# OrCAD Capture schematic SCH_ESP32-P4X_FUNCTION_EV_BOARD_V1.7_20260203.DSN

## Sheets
1 01_DESIGNBLOCK: title: ESP32-P4X_FUNCTION_EV_BOARD; rev: 1.7; note: 01_DESIGNBLOCK
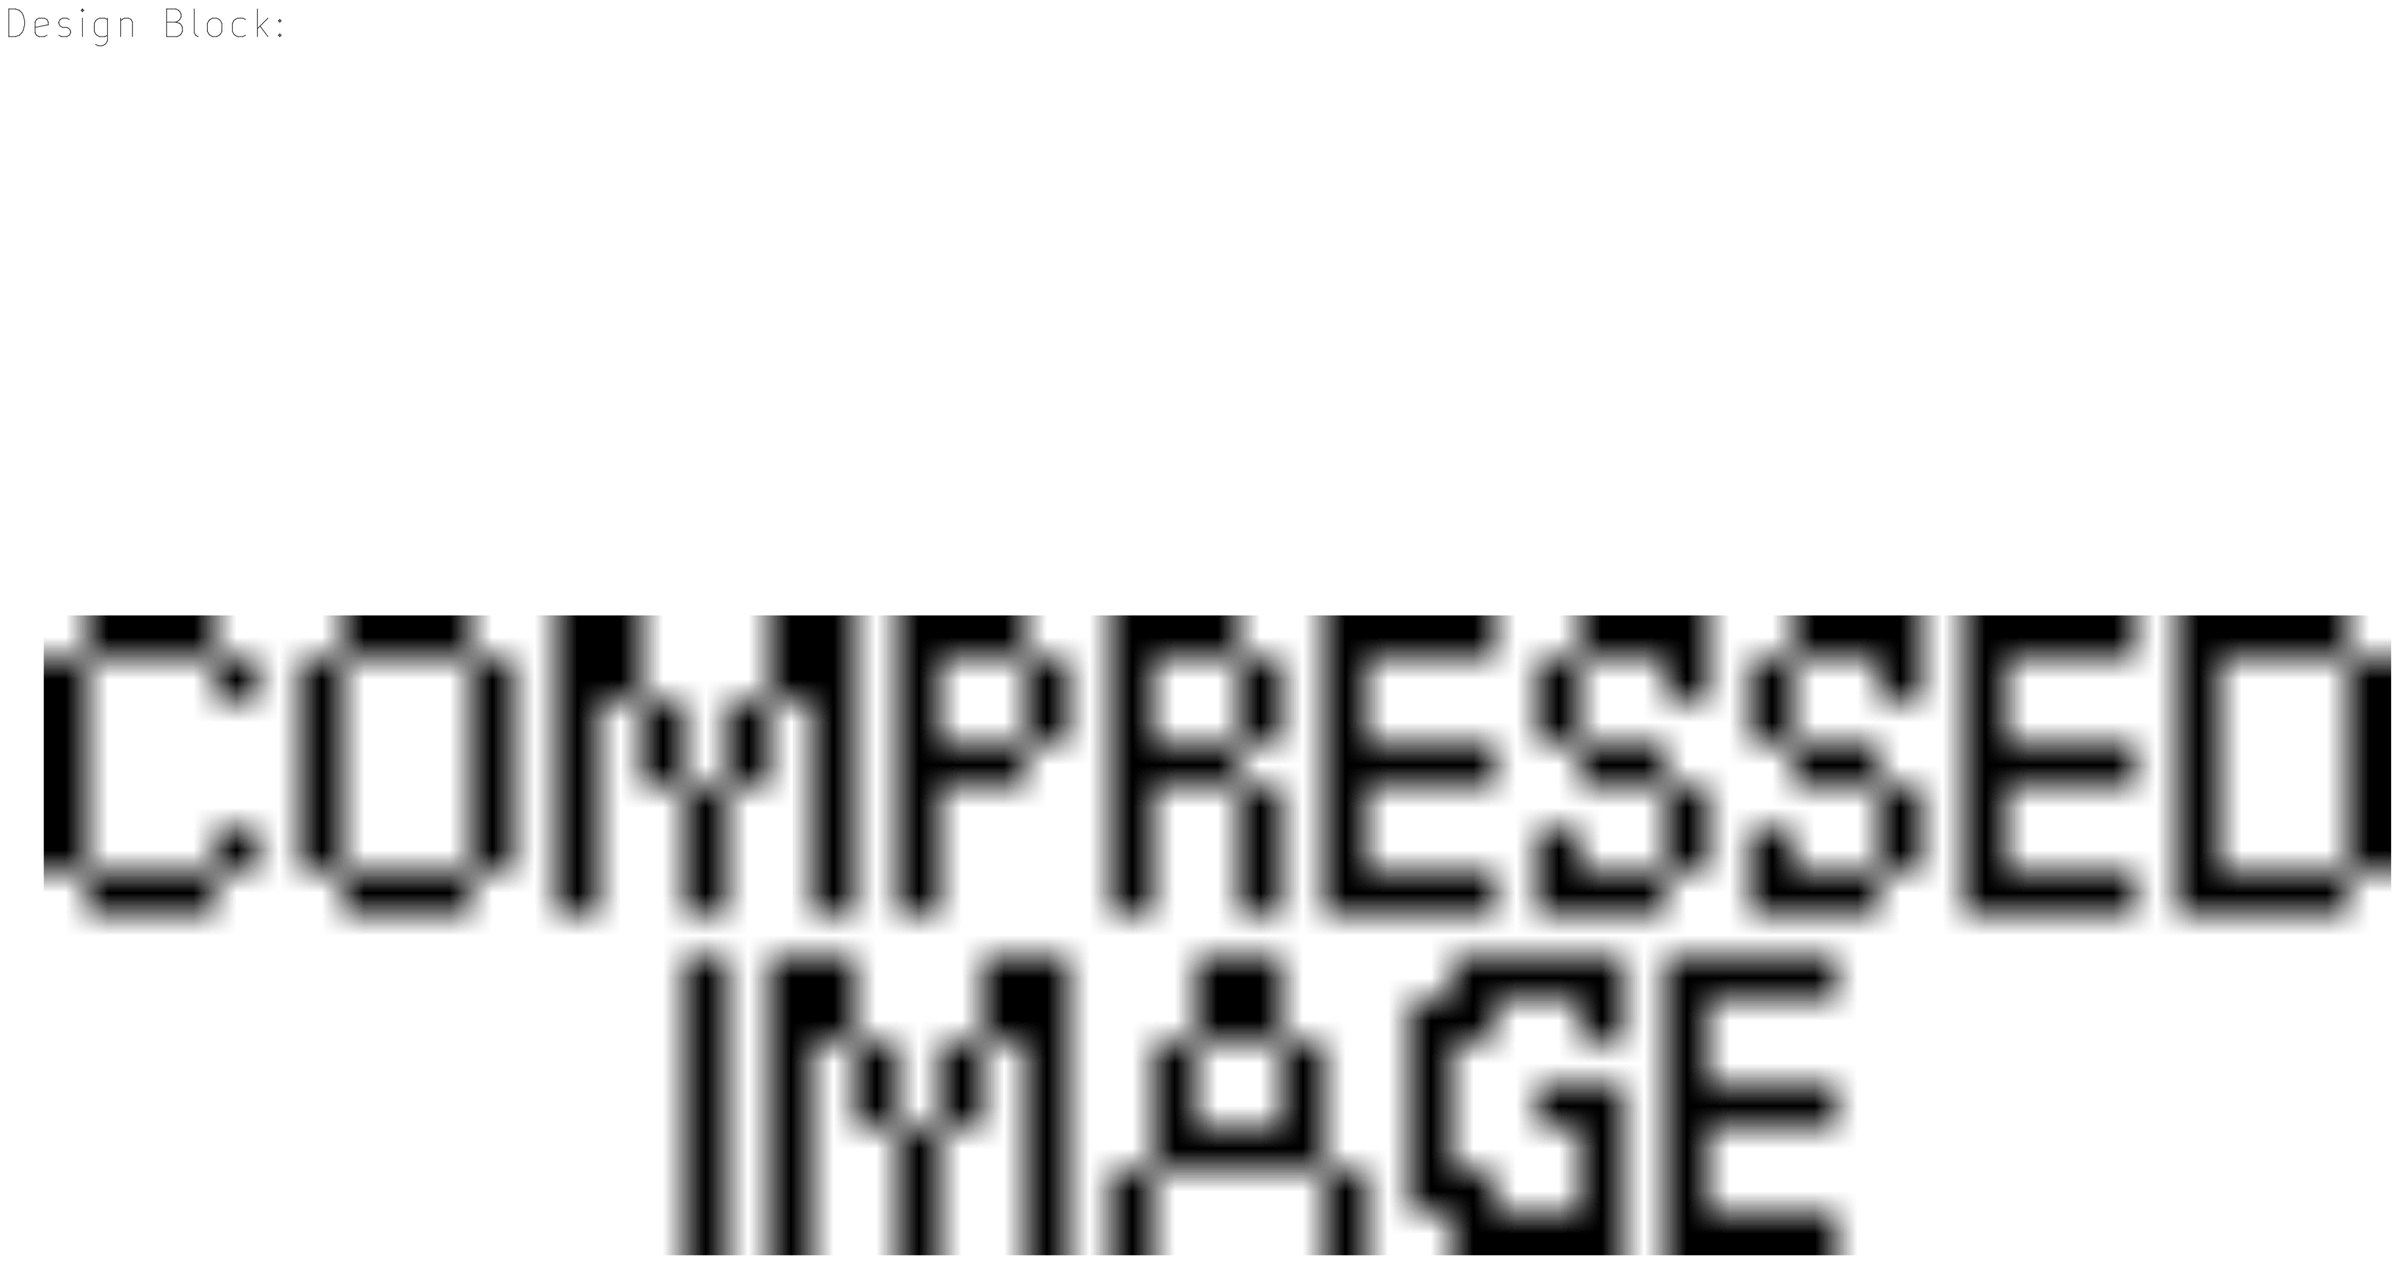
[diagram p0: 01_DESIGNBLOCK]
2 02_ESP32-P4: size C; note: 02_ESP32-P4
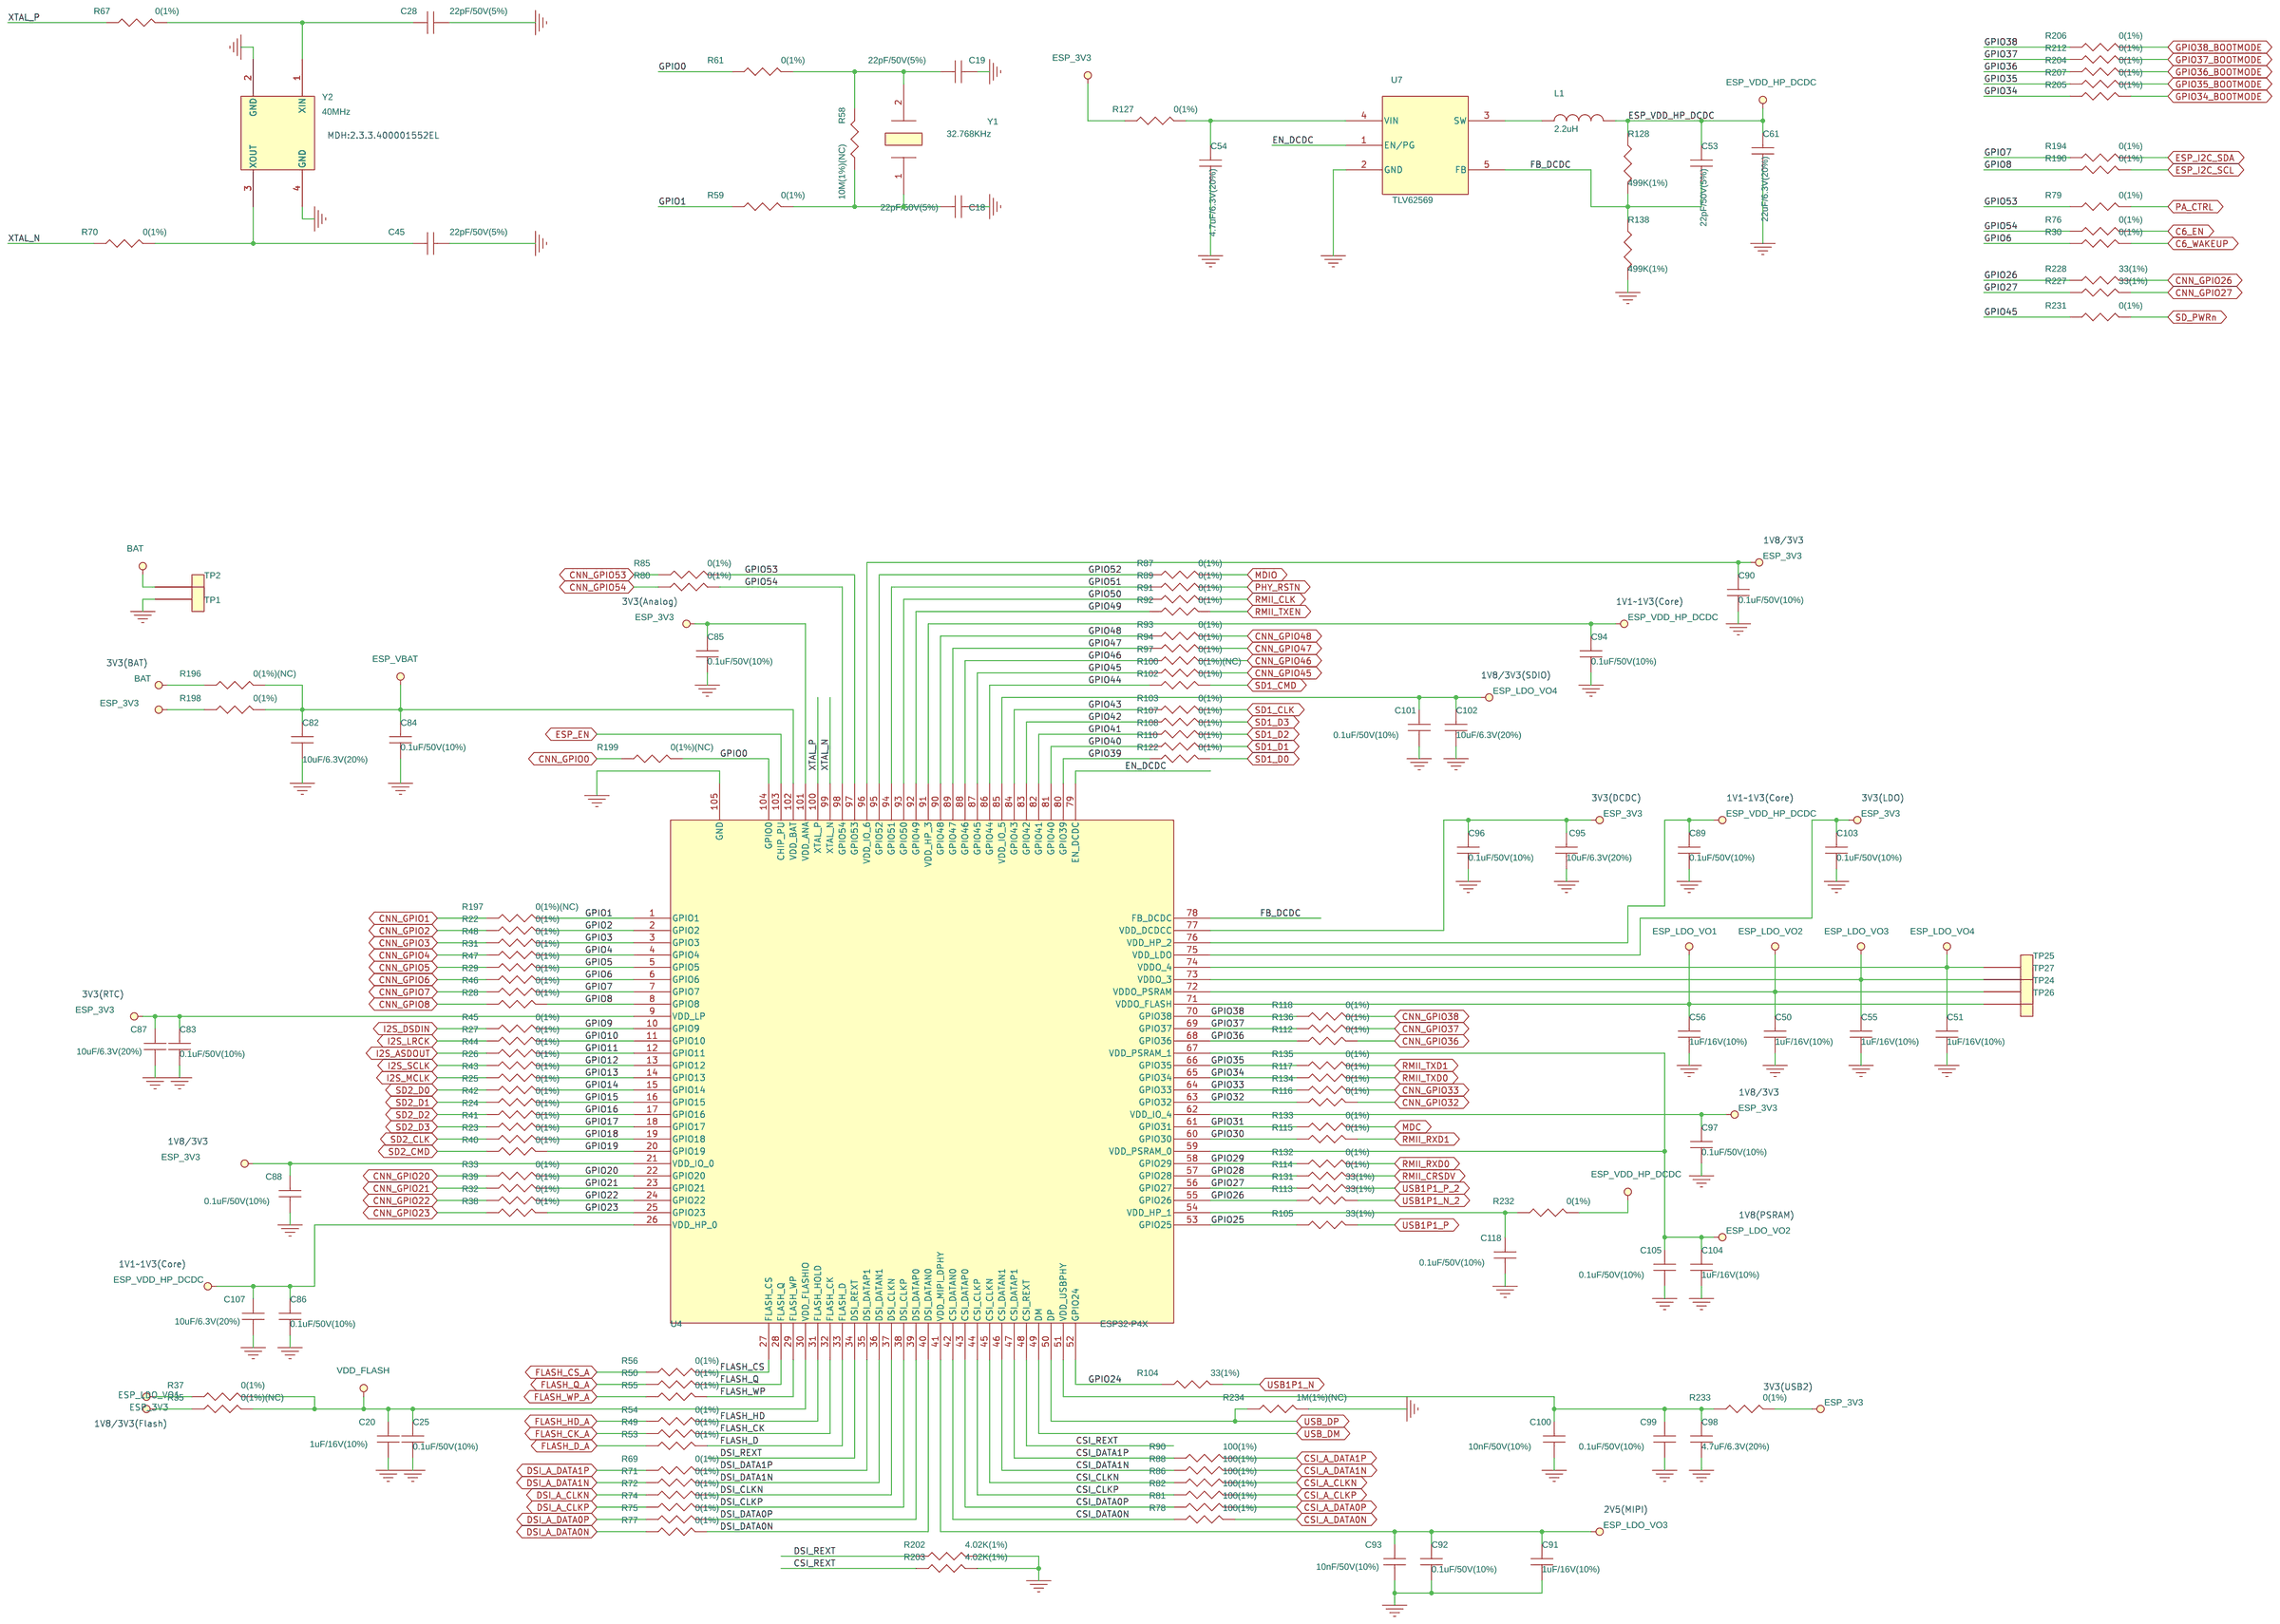
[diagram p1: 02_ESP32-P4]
3 04_Audio: size C; note: 04_Audio
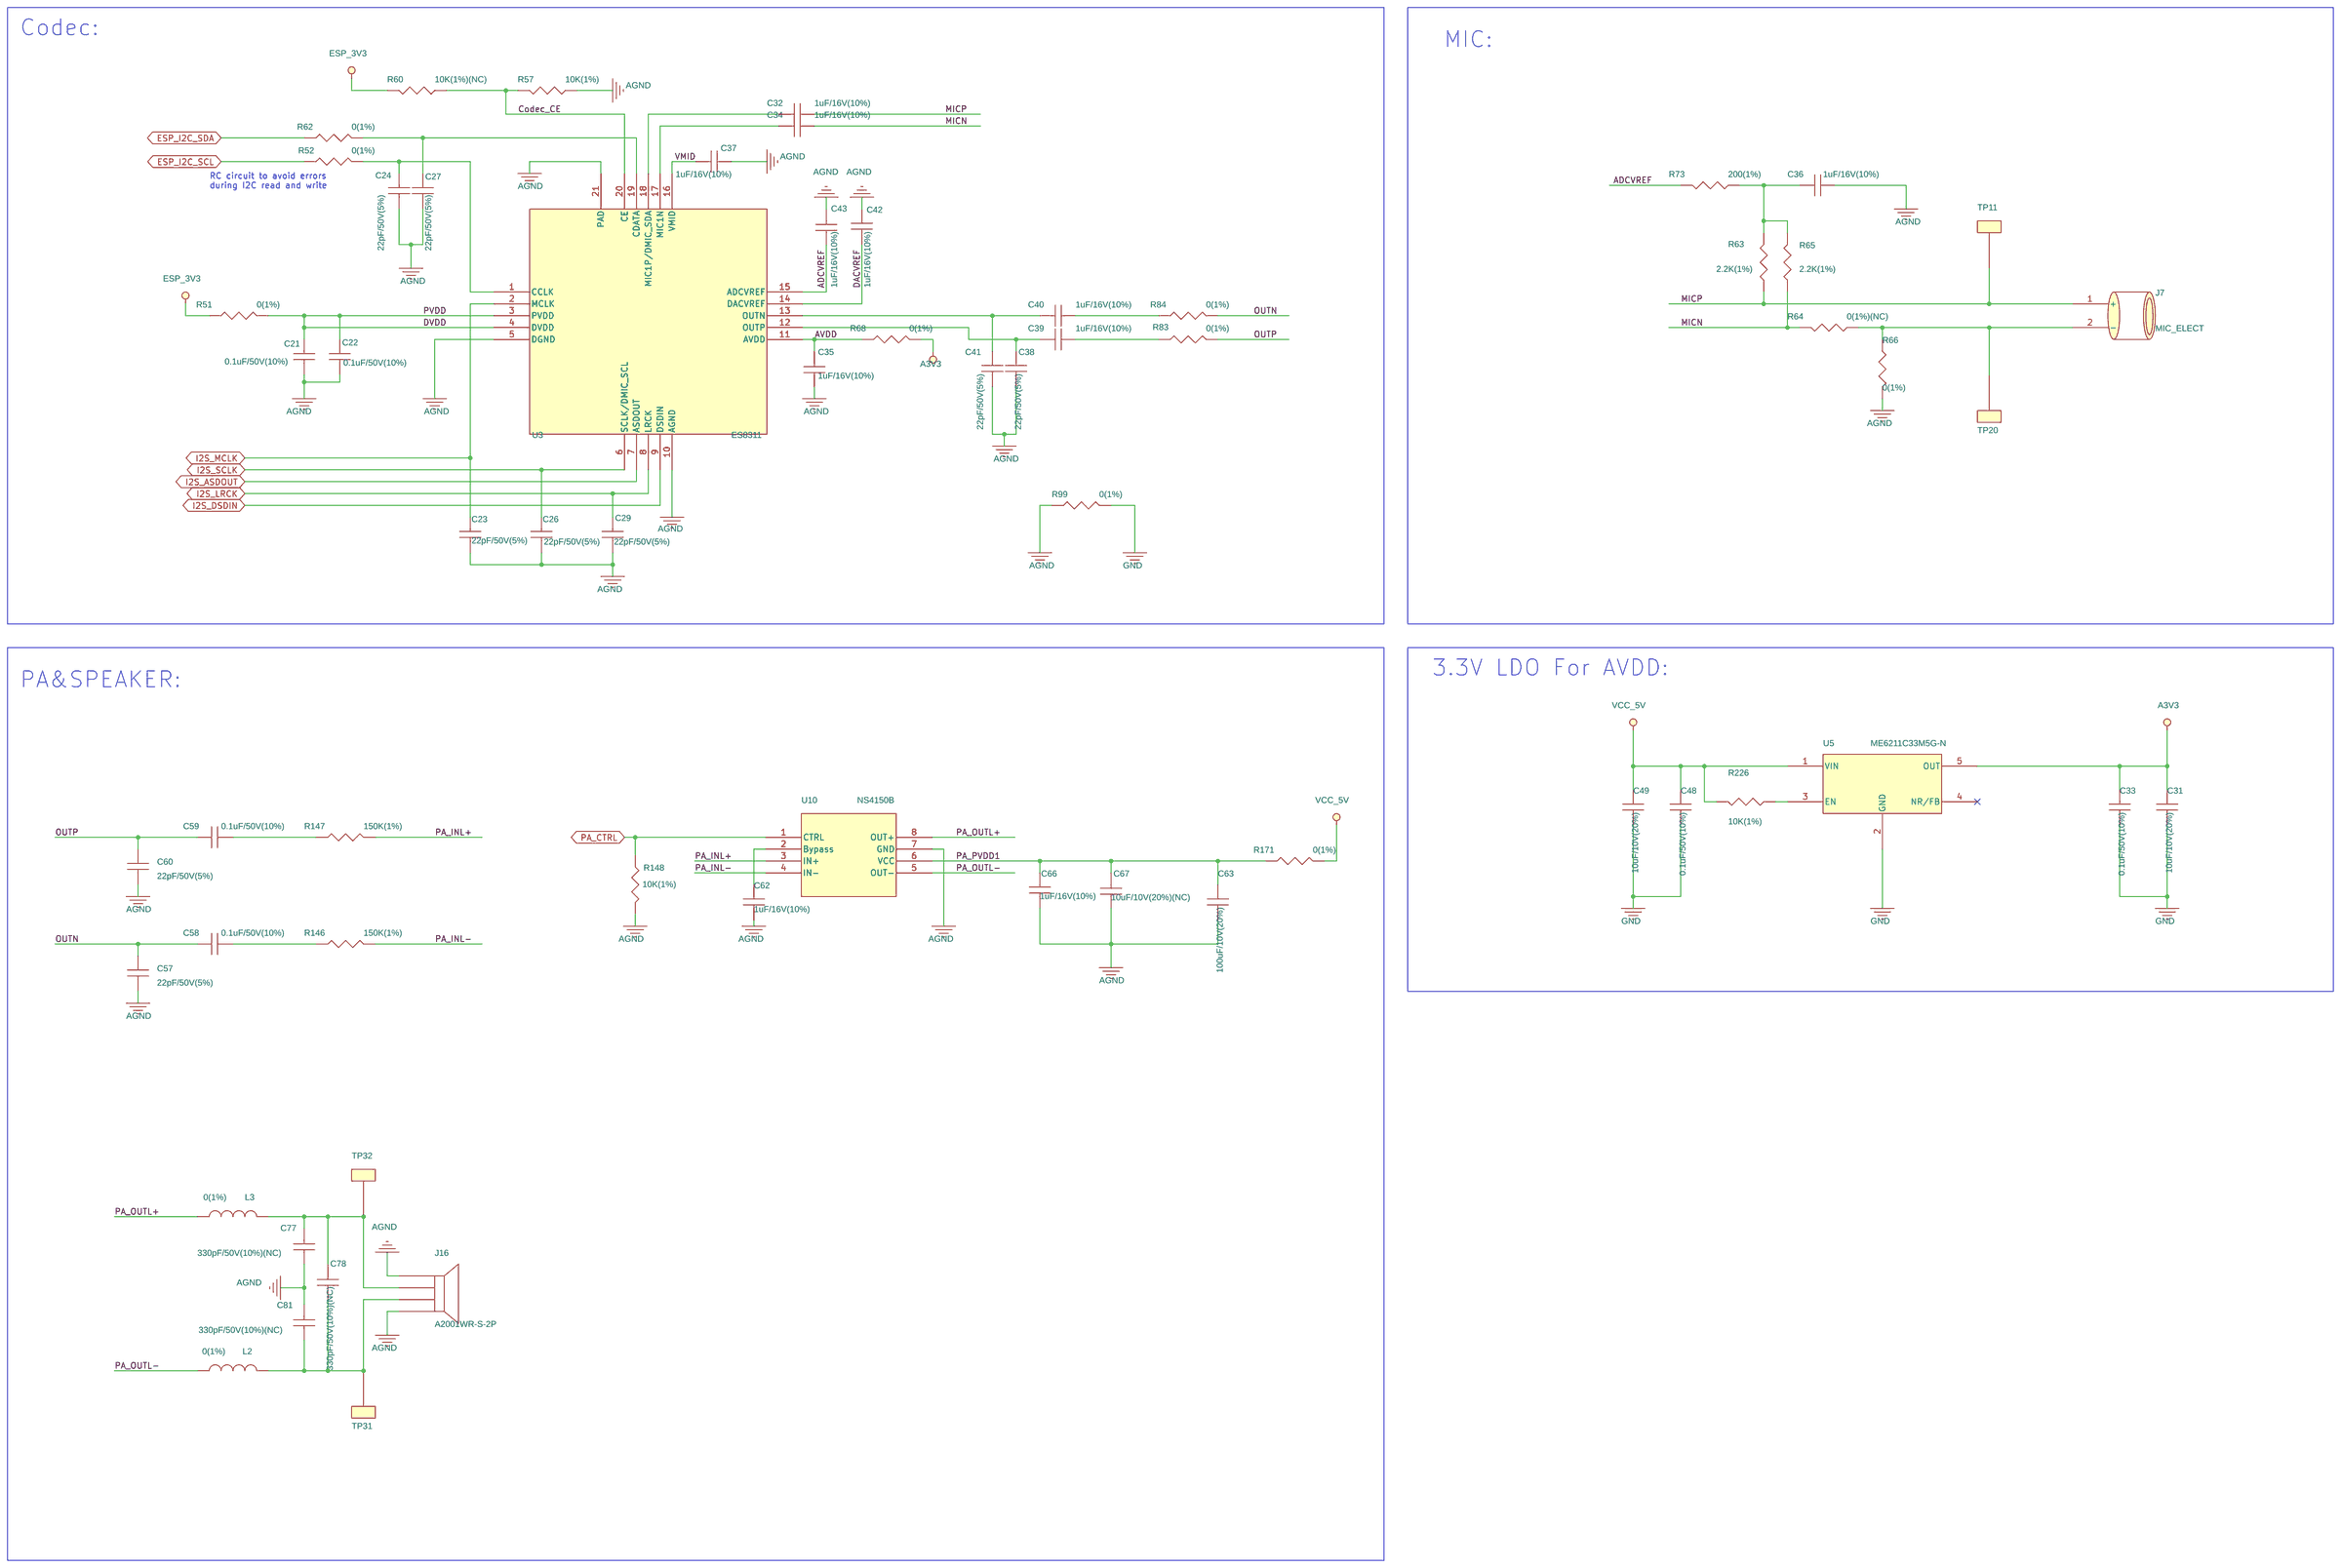
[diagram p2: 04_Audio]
4 05_Ethernet_SDMMC_WiFi: size C; note: 05_Ethernet_SDMMC_WiFi
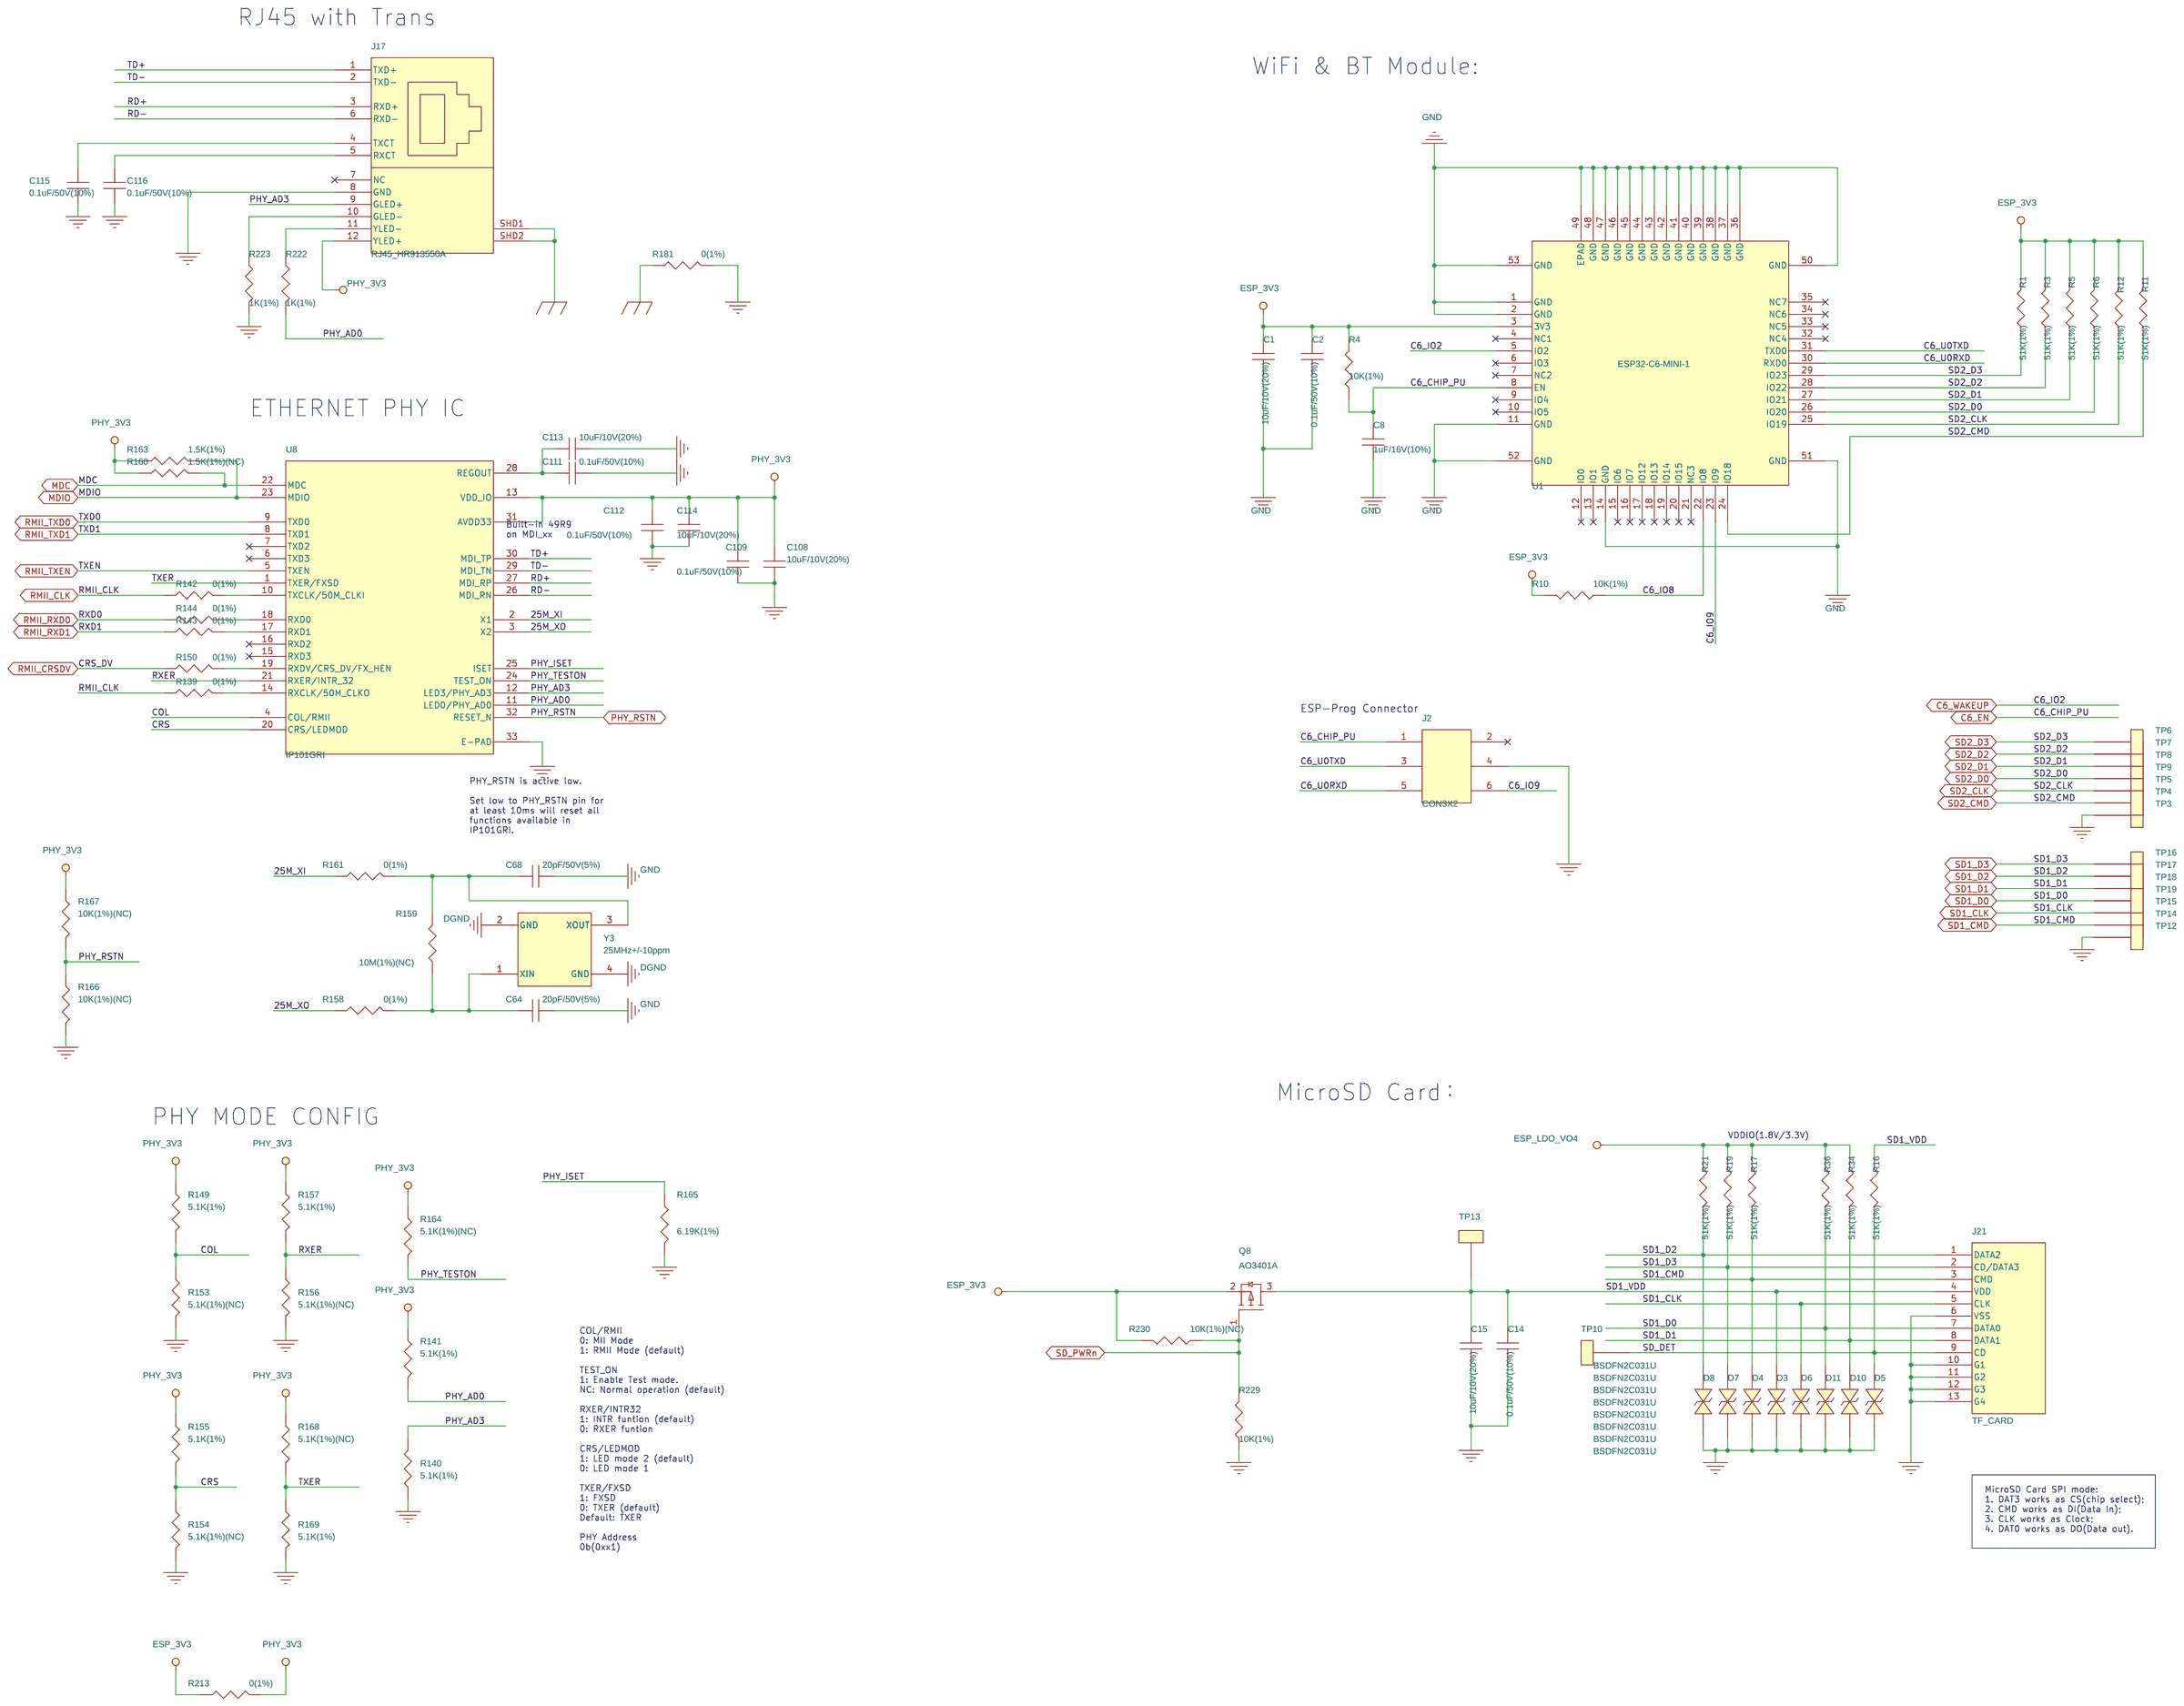
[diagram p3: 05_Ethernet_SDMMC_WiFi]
5 03_FLASH_DBG_CNN: size C; note: 03_FLASH_DBG_CNN
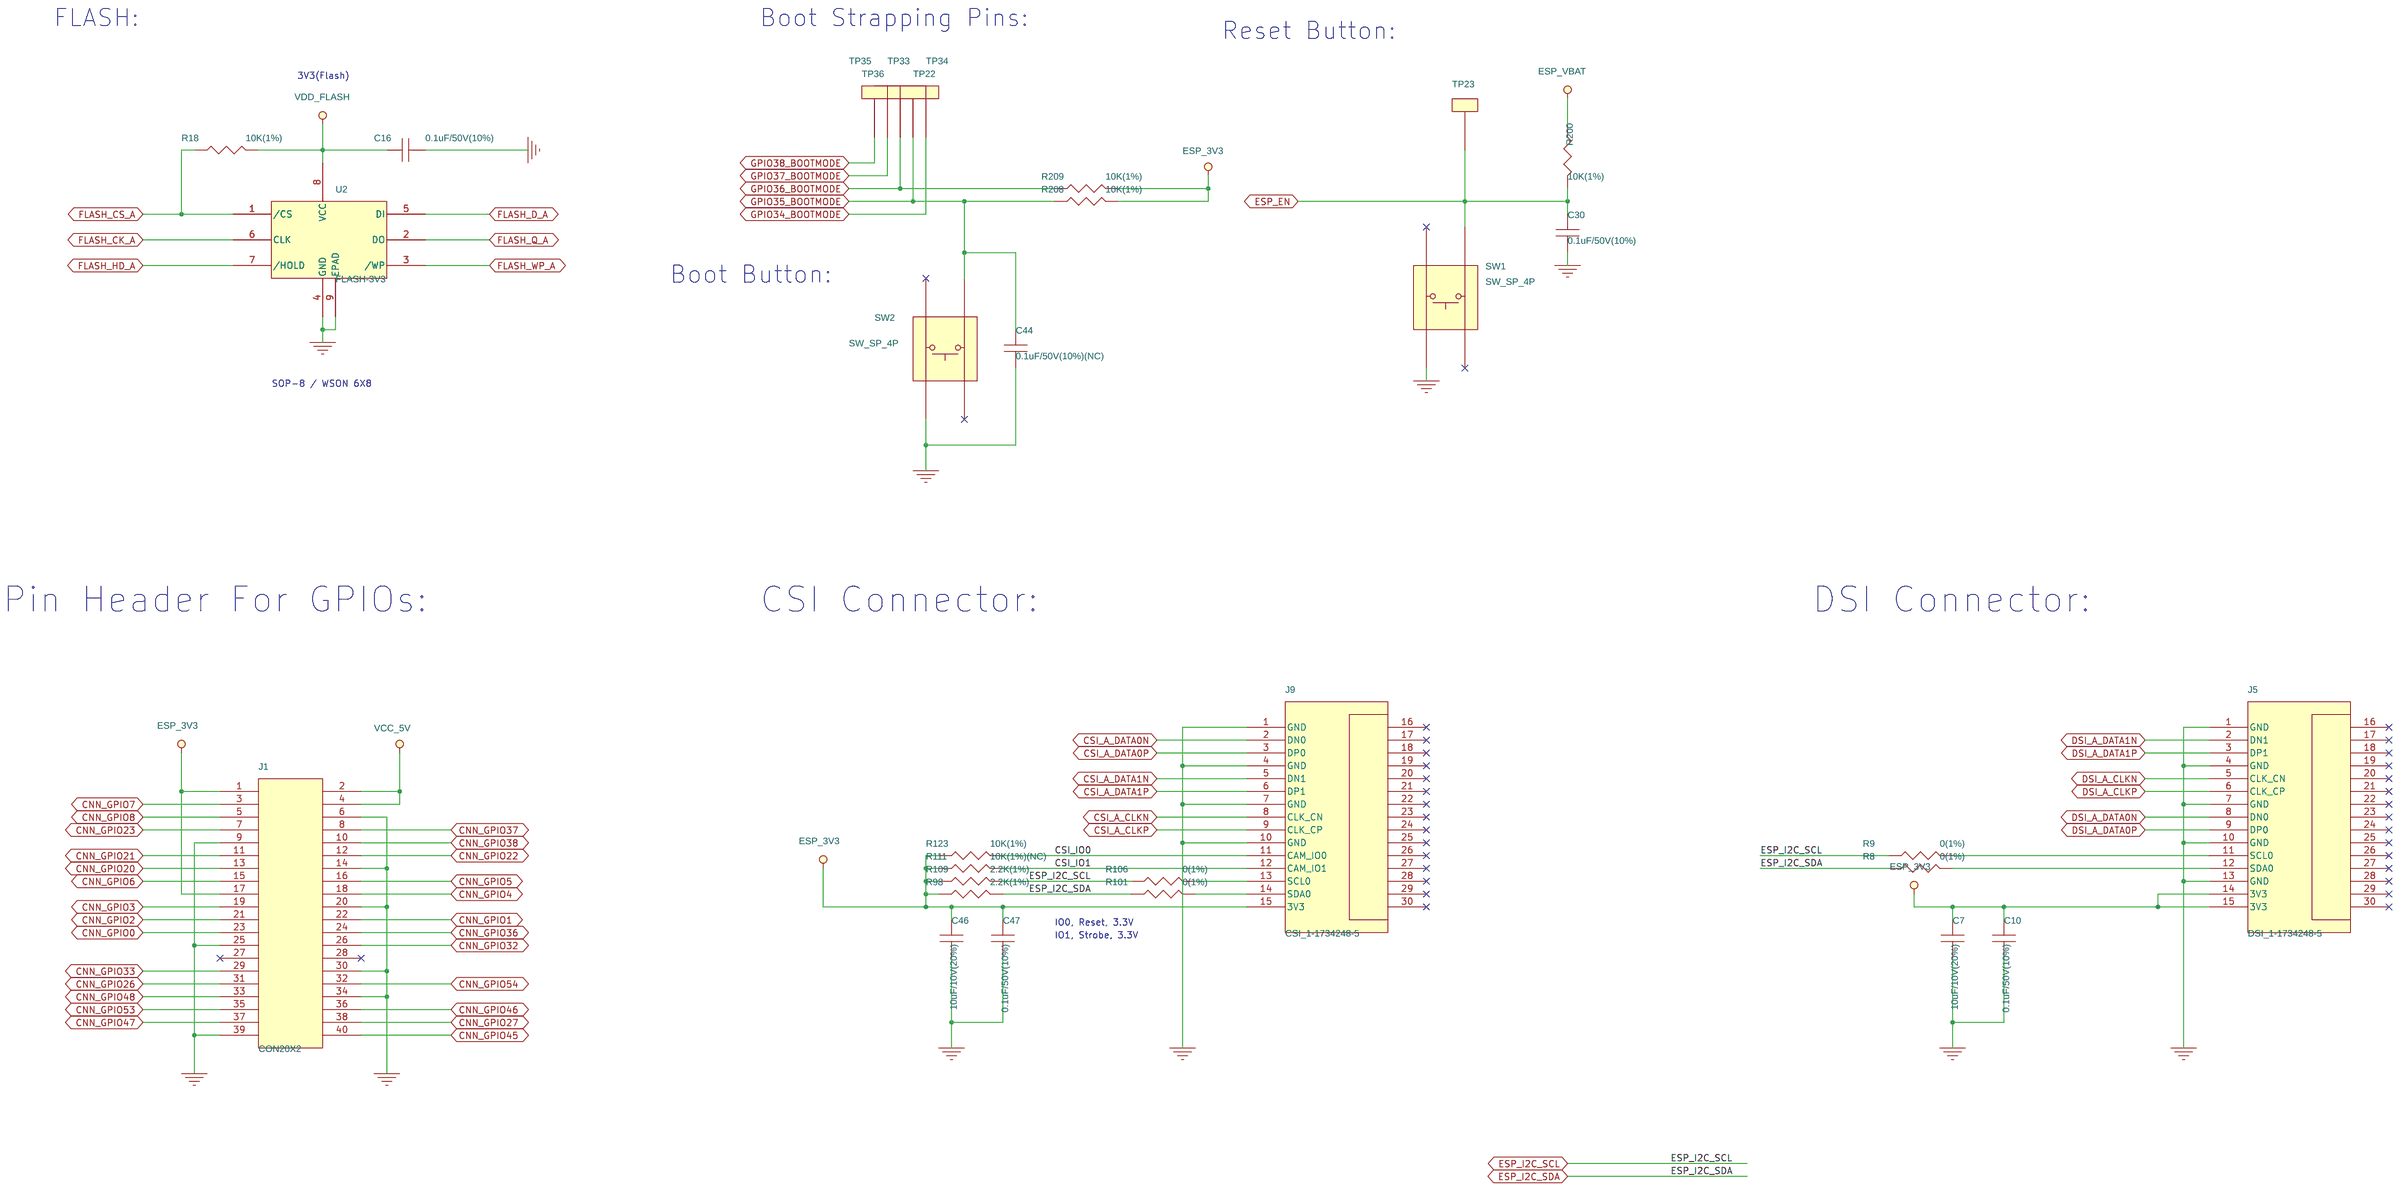
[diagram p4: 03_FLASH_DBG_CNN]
6 06_SYS_PWR_USB: size C; note: 06_SYS_PWR_USB
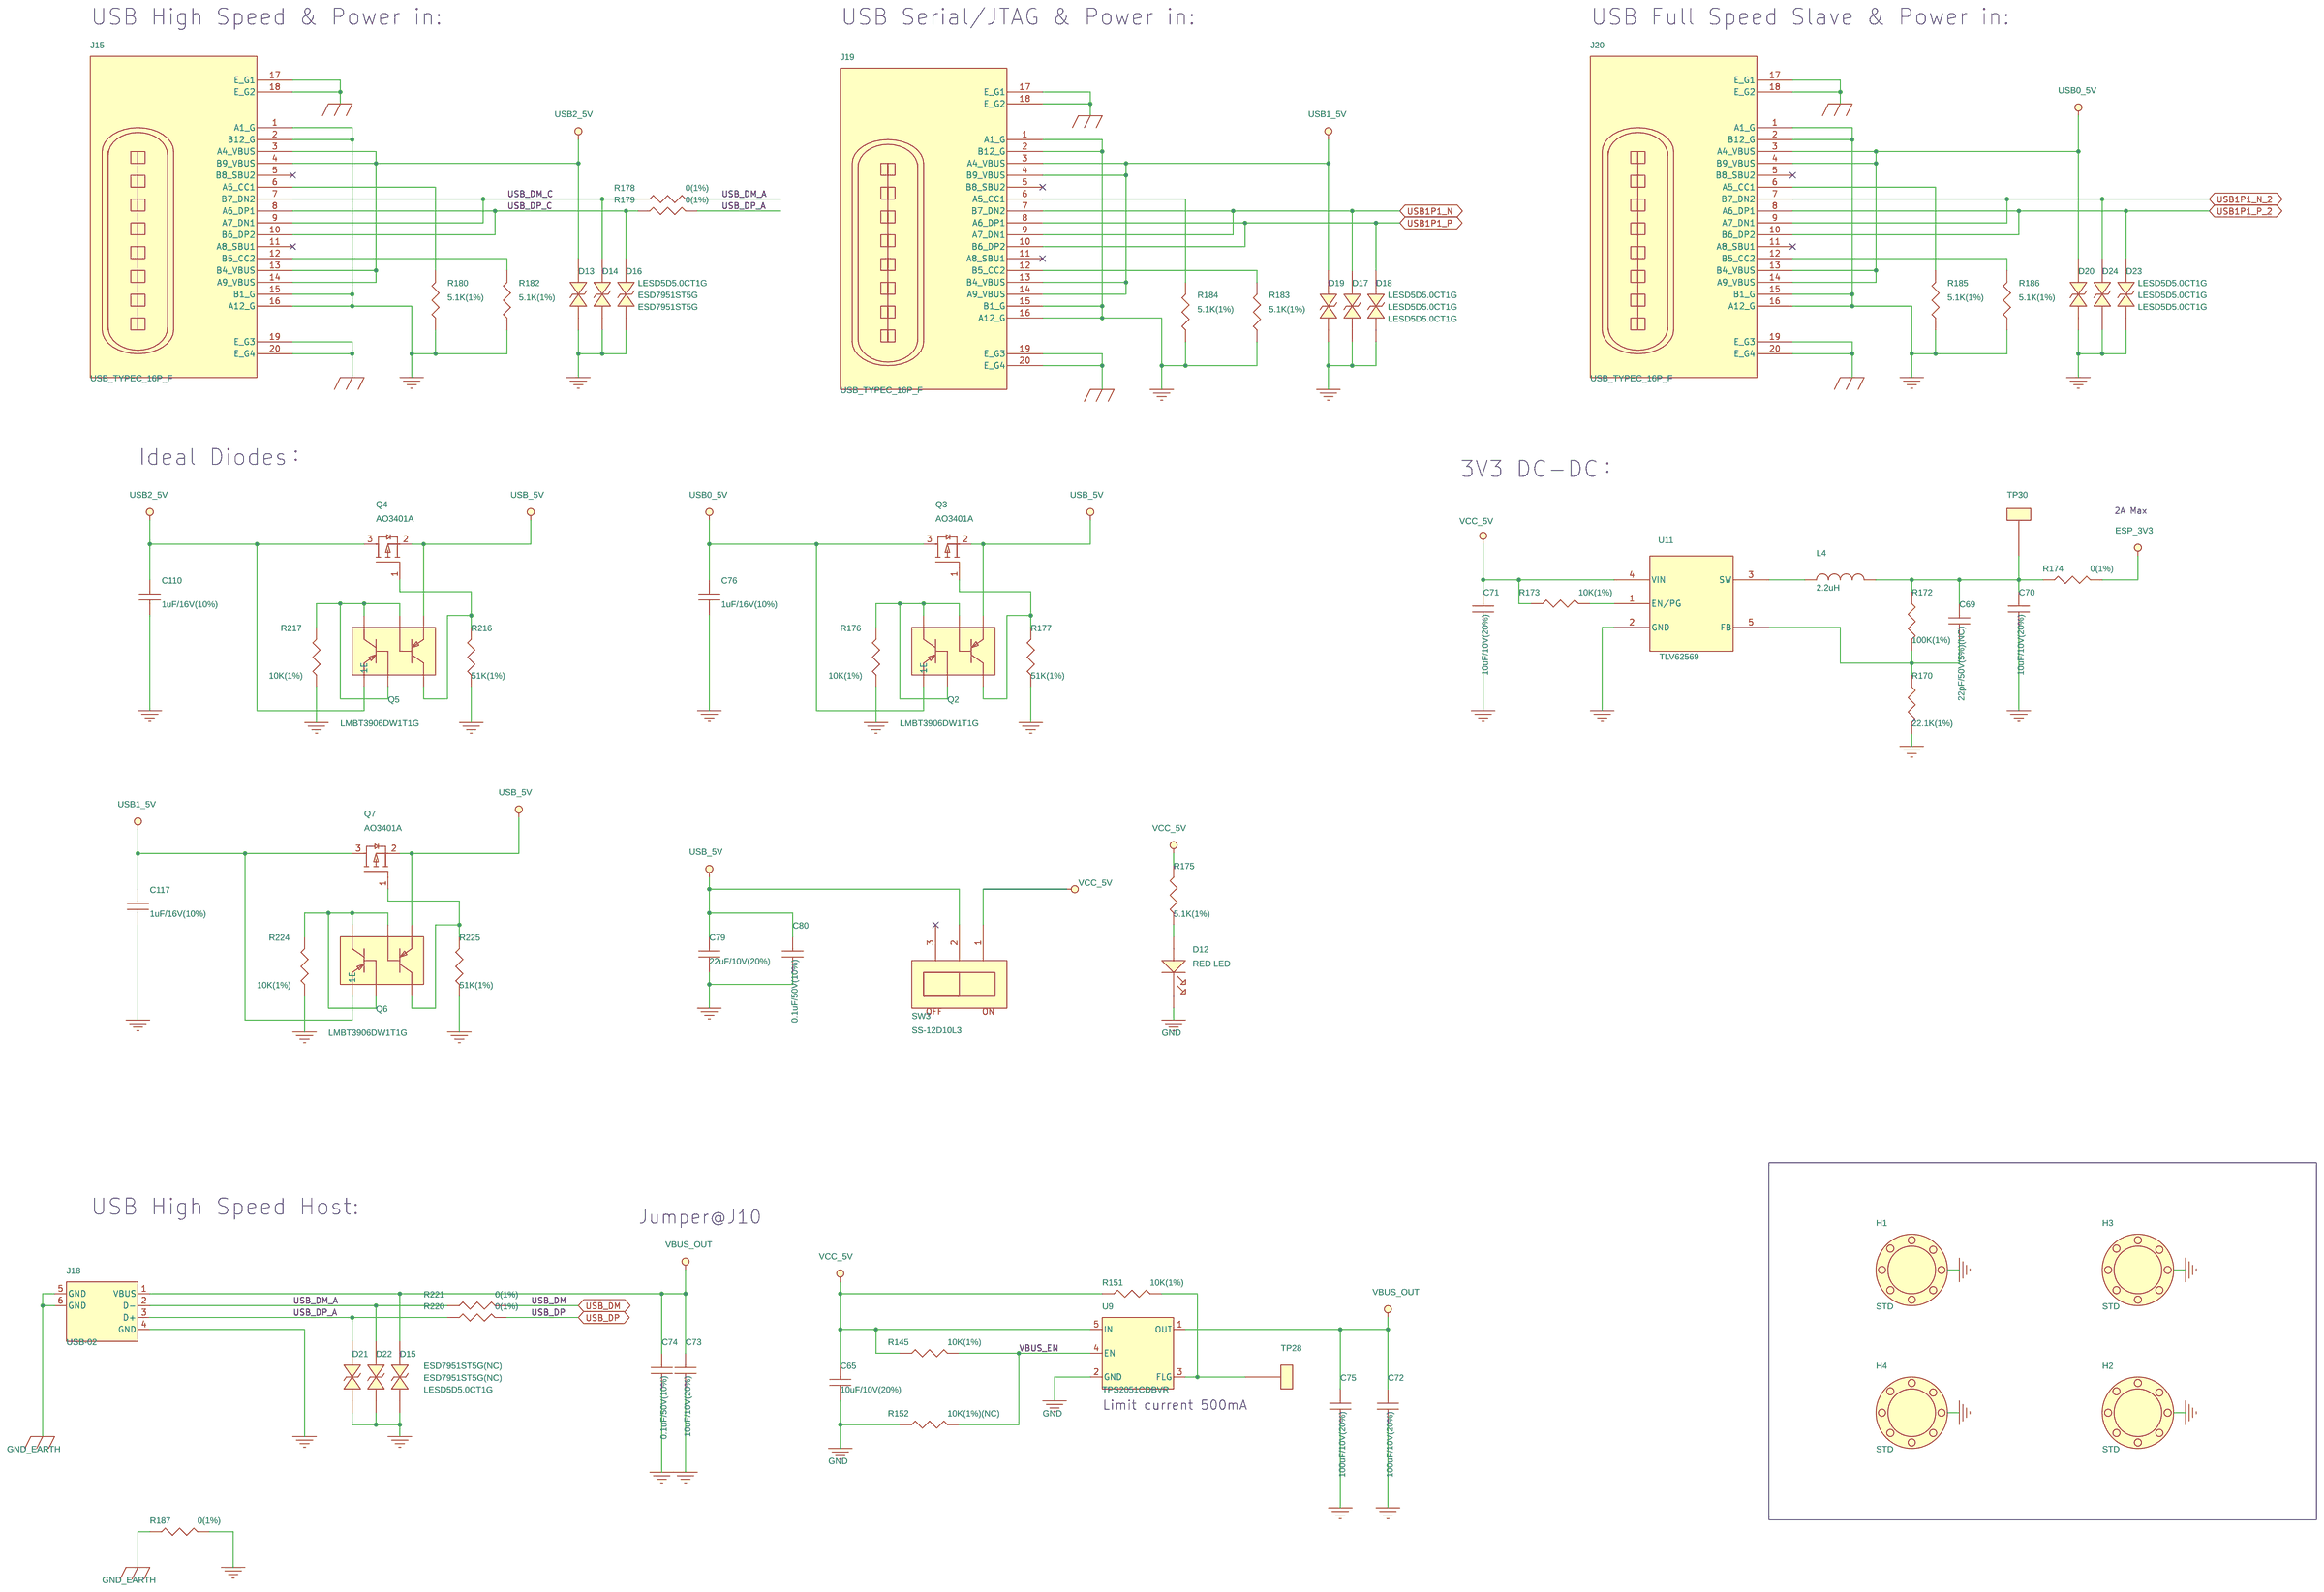
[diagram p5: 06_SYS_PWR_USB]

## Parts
sheet 02_ESP32-P4
C18  22pF/50V(5%)  [C0402]
C19  22pF/50V(5%)  [C0402]
C20  1uF/16V(10%)  [C0402]
C25  0.1uF/50V(10%)  [C0402]
C28  22pF/50V(5%)  [C0402]
C45  22pF/50V(5%)  [C0402]
C50  1uF/16V(10%)  [C0402]
C51  1uF/16V(10%)  [C0402]
C53  22pF/50V(5%)  [C0402]
C54  4.7uF/6.3V(20%)  [C0402]
C55  1uF/16V(10%)  [C0402]
C56  1uF/16V(10%)  [C0402]
C61  22uF/6.3V(20%)  [C0402]
C82  10uF/6.3V(20%)  [C0402]
C83  0.1uF/50V(10%)  [C0402]
C84  0.1uF/50V(10%)  [C0402]
C85  0.1uF/50V(10%)  [C0402]
C86  0.1uF/50V(10%)  [C0402]
C87  10uF/6.3V(20%)  [C0402]
C88  0.1uF/50V(10%)  [C0402]
C89  0.1uF/50V(10%)  [C0402]
C90  0.1uF/50V(10%)  [C0402]
C91  1uF/16V(10%)  [C0402]
C92  0.1uF/50V(10%)  [C0402]
C93  10nF/50V(10%)  [C0402]
C94  0.1uF/50V(10%)  [C0402]
C95  10uF/6.3V(20%)  [C0402]
C96  0.1uF/50V(10%)  [C0402]
C97  0.1uF/50V(10%)  [C0402]
C98  4.7uF/6.3V(20%)  [C0402]
C99  0.1uF/50V(10%)  [C0402]
C100  10nF/50V(10%)  [C0402]
C101  0.1uF/50V(10%)  [C0402]
C102  10uF/6.3V(20%)  [C0402]
C103  0.1uF/50V(10%)  [C0402]
C104  1uF/16V(10%)  [C0402]
C105  0.1uF/50V(10%)  [C0402]
C107  10uF/6.3V(20%)  [C0402]
C118  0.1uF/50V(10%)  [C0402]
L1  2.2uH  [L2520]
R22  0(1%)  [R0402]
R23  0(1%)  [R0402]
R24  0(1%)  [R0402]
R25  0(1%)  [R0402]
R26  0(1%)  [R0402]
R27  0(1%)  [R0402]
R28  0(1%)  [R0402]
R29  0(1%)  [R0402]
R30  0(1%)  [R0402]
R31  0(1%)  [R0402]
R32  0(1%)  [R0402]
R33  0(1%)  [R0402]
R35  0(1%)(NC)  [R0402]
R37  0(1%)  [R0402]
R38  0(1%)  [R0402]
R39  0(1%)  [R0402]
R40  0(1%)  [R0402]
R41  0(1%)  [R0402]
R42  0(1%)  [R0402]
R43  0(1%)  [R0402]
R44  0(1%)  [R0402]
R45  0(1%)  [R0402]
R46  0(1%)  [R0402]
R47  0(1%)  [R0402]
R48  0(1%)  [R0402]
R49  0(1%)  [R0402]
R50  0(1%)  [R0402]
R53  0(1%)  [R0402]
R54  0(1%)  [R0402]
R55  0(1%)  [R0402]
R56  0(1%)  [R0402]
R58  10M(1%)(NC)  [R0402]
R59  0(1%)  [R0402]
R61  0(1%)  [R0402]
R67  0(1%)  [R0402]
R69  0(1%)  [R0201]
R70  0(1%)  [R0402]
R71  0(1%)  [R0201]
R72  0(1%)  [R0201]
R74  0(1%)  [R0201]
R75  0(1%)  [R0201]
R76  0(1%)  [R0402]
R77  0(1%)  [R0201]
R78  100(1%)  [R0201]
R79  0(1%)  [R0402]
R80  0(1%)  [R0402]
R81  100(1%)  [R0201]
R82  100(1%)  [R0201]
R85  0(1%)  [R0402]
R86  100(1%)  [R0201]
R87  0(1%)  [R0402]
R88  100(1%)  [R0201]
R89  0(1%)  [R0402]
R90  100(1%)  [R0201]
R91  0(1%)  [R0402]
R92  0(1%)  [R0402]
R93  0(1%)  [R0402]
R94  0(1%)  [R0402]
R97  0(1%)  [R0402]
R100  0(1%)(NC)  [R0402]
R102  0(1%)  [R0402]
R103  0(1%)  [R0402]
R104  33(1%)  [R0402]
R105  33(1%)  [R0402]
R107  0(1%)  [R0402]
R108  0(1%)  [R0402]
R110  0(1%)  [R0402]
R112  0(1%)  [R0402]
R113  33(1%)  [R0402]
R114  0(1%)  [R0402]
R115  0(1%)  [R0402]
R116  0(1%)  [R0402]
R117  0(1%)  [R0402]
R118  0(1%)  [R0402]
R122  0(1%)  [R0402]
R127  0(1%)  [R0603]
R128  499K(1%)  [R0402]
R131  33(1%)  [R0402]
R132  0(1%)  [R0402]
R133  0(1%)  [R0402]
R134  0(1%)  [R0402]
R135  0(1%)  [R0402]
R136  0(1%)  [R0402]
R138  499K(1%)  [R0402]
R190  0(1%)  [R0402]
R194  0(1%)  [R0402]
R196  0(1%)(NC)  [R0402]
R197  0(1%)(NC)  [R0402]
R198  0(1%)  [R0402]
R199  0(1%)(NC)  [R0402]
R202  4.02K(1%)  [R0402]
R203  4.02K(1%)  [R0402]
R204  0(1%)  [R0402]
R205  0(1%)  [R0402]
R206  0(1%)  [R0402]
R207  0(1%)  [R0402]
R212  0(1%)  [R0402]
R227  33(1%)  [R0402]
R228  33(1%)  [R0402]
R231  0(1%)  [R0402]
R232  0(1%)  [R0402]
R233  0(1%)  [R0402]
R234  1M(1%)(NC)  [R0402]
TP1  TESTPOINT  [TPC1]
TP2  TESTPOINT  [TPC1]
TP24  TESTPOINT  [TPC1]
TP25  TESTPOINT  [TPC1]
TP26  TESTPOINT  [TPC1]
TP27  TESTPOINT  [TPC1]
U4  ESP32-P4X  [qfn104_0p35_10_e7p5_a]
U7  TLV62569  [sot23_0P95_2P6]
Y1  32.768KHz  [XTAL3215]
Y2  40MHz  [XTAL3225]
sheet 03_FLASH_DBG_CNN
C7  10uF/10V(20%)  [C0603]
C10  0.1uF/50V(10%)  [C0402]
C16  0.1uF/50V(10%)  [C0402]
C30  0.1uF/50V(10%)  [C0402]
C44  0.1uF/50V(10%)(NC)  [C0402]
C46  10uF/10V(20%)  [C0603]
C47  0.1uF/50V(10%)  [C0402]
J1  CON20X2  [CON20X2_2P54]
J5  DSI_1-1734248-5  [FFC_15P_1_MIPI]
J9  CSI_1-1734248-5  [FFC_15P_1_MIPI]
R8  0(1%)  [R0402]
R9  0(1%)  [R0402]
R18  10K(1%)  [R0402]
R98  2.2K(1%)  [R0402]
R101  0(1%)  [R0402]
R106  0(1%)  [R0402]
R109  2.2K(1%)  [R0402]
R111  10K(1%)(NC)  [R0402]
R123  10K(1%)  [R0402]
R200  10K(1%)  [R0402]
R208  10K(1%)  [R0402]
R209  10K(1%)  [R0402]
SW1  SW_SP_4P  [SW4-4P5X4P5X2P9-SMT]
SW2  SW_SP_4P  [SW4-4P5X4P5X2P9-SMT]
TP22  TESTPOINT  [TPC1]
TP23  TESTPOINT  [TPC1]
TP33  TESTPOINT  [TPC1]
TP34  TESTPOINT  [TPC1]
TP35  TESTPOINT  [TPC1]
TP36  TESTPOINT  [TPC1]
U2  FLASH-3V3  [wson6x8]
sheet 04_Audio
C21  0.1uF/50V(10%)  [C0402]
C22  0.1uF/50V(10%)  [C0402]
C23  22pF/50V(5%)  [C0402]
C24  22pF/50V(5%)  [C0402]
C26  22pF/50V(5%)  [C0402]
C27  22pF/50V(5%)  [C0402]
C29  22pF/50V(5%)  [C0402]
C31  10uF/10V(20%)  [C0603]
C32  1uF/16V(10%)  [C0402]
C33  0.1uF/50V(10%)  [C0402]
C34  1uF/16V(10%)  [C0402]
C35  1uF/16V(10%)  [C0402]
C36  1uF/16V(10%)  [C0402]
C37  1uF/16V(10%)  [C0402]
C38  22pF/50V(5%)  [C0402]
C39  1uF/16V(10%)  [C0402]
C40  1uF/16V(10%)  [C0402]
C41  22pF/50V(5%)  [C0402]
C42  1uF/16V(10%)  [C0402]
C43  1uF/16V(10%)  [C0402]
C48  0.1uF/50V(10%)  [C0402]
C49  10uF/10V(20%)  [C0603]
C57  22pF/50V(5%)  [C0402]
C58  0.1uF/50V(10%)  [C0402]
C59  0.1uF/50V(10%)  [C0402]
C60  22pF/50V(5%)  [C0402]
C62  1uF/16V(10%)  [C0402]
C63  100uF/10V(20%)  [C1206]
C66  1uF/16V(10%)  [C0402]
C67  10uF/10V(20%)(NC)  [C0603]
C77  330pF/50V(10%)(NC)  [C0402]
C78  330pF/50V(10%)(NC)  [C0402]
C81  330pF/50V(10%)(NC)  [C0402]
J7  MIC_ELECT  [mic2_4_B4013AM422-042]
J16  A2001WR-S-2P  [CON2X1_2P0_SMT_PH2A-S-A]
L2  0(1%)  [R0603]
L3  0(1%)  [R0603]
R51  0(1%)  [R0402]
R52  0(1%)  [R0402]
R57  10K(1%)  [R0402]
R60  10K(1%)(NC)  [R0402]
R62  0(1%)  [R0402]
R63  2.2K(1%)  [R0402]
R64  0(1%)(NC)  [R0402]
R65  2.2K(1%)  [R0402]
R66  0(1%)  [R0402]
R68  0(1%)  [R0402]
R73  200(1%)  [R0402]
R83  0(1%)  [R0402]
R84  0(1%)  [R0402]
R99  0(1%)  [R0603]
R146  150K(1%)  [R0402]
R147  150K(1%)  [R0402]
R148  10K(1%)  [R0402]
R171  0(1%)  [R0603]
R226  10K(1%)  [R0402]
TP11  TESTPOINT  [TPC1]
TP20  TESTPOINT  [TPC1]
TP31  TESTPOINT  [TPC1]
TP32  TESTPOINT  [TPC1]
U3  ES8311  [QFN20_0P4_3]
U5  ME6211C33M5G-N  [SOT23-5]
U10  NS4150B  [SSOP8_0P65_5]
sheet 05_Ethernet_SDMMC_WiFi
C1  10uF/10V(20%)  [C0603]
C2  0.1uF/50V(10%)  [C0402]
C8  1uF/16V(10%)  [C0402]
C14  0.1uF/50V(10%)  [C0402]
C15  10uF/10V(20%)  [C0603]
C64  20pF/50V(5%)  [C0402]
C68  20pF/50V(5%)  [C0402]
C108  10uF/10V(20%)  [C0603]
C109  0.1uF/50V(10%)  [C0402]
C111  0.1uF/50V(10%)  [C0402]
C112  0.1uF/50V(10%)  [C0402]
C113  10uF/10V(20%)  [C0603]
C114  10uF/10V(20%)  [C0603]
C115  0.1uF/50V(10%)  [C0402]
C116  0.1uF/50V(10%)  [C0402]
D3  BSDFN2C031U  [SOD882]
D4  BSDFN2C031U  [SOD882]
D5  BSDFN2C031U  [SOD882]
D6  BSDFN2C031U  [SOD882]
D7  BSDFN2C031U  [SOD882]
D8  BSDFN2C031U  [SOD882]
D10  BSDFN2C031U  [SOD882]
D11  BSDFN2C031U  [SOD882]
J2  CON3X2  [con3x2_2p54]
J17  RJ45_HR913550A  [RJ45_HR913129A]
J21  TF_CARD  [tf_carda]
Q8  AO3401A  [SOT23-3]
R1  51K(1%)  [R0402]
R3  51K(1%)  [R0402]
R4  10K(1%)  [R0402]
R5  51K(1%)  [R0402]
R6  51K(1%)  [R0402]
R10  10K(1%)  [R0402]
R11  51K(1%)  [R0402]
R12  51K(1%)  [R0402]
R16  51K(1%)  [R0402]
R17  51K(1%)  [R0402]
R19  51K(1%)  [R0402]
R21  51K(1%)  [R0402]
R34  51K(1%)  [R0402]
R36  51K(1%)  [R0402]
R139  0(1%)  [R0402]
R140  5.1K(1%)  [R0402]
R141  5.1K(1%)  [R0402]
R142  0(1%)  [R0402]
R143  0(1%)  [R0402]
R144  0(1%)  [R0402]
R149  5.1K(1%)  [R0402]
R150  0(1%)  [R0402]
R153  5.1K(1%)(NC)  [R0402]
R154  5.1K(1%)(NC)  [R0402]
R155  5.1K(1%)  [R0402]
R156  5.1K(1%)(NC)  [R0402]
R157  5.1K(1%)  [R0402]
R158  0(1%)  [R0402]
R159  10M(1%)(NC)  [R0402]
R160  1.5K(1%)(NC)  [R0402]
R161  0(1%)  [R0402]
R163  1.5K(1%)  [R0402]
R164  5.1K(1%)(NC)  [R0402]
R165  6.19K(1%)  [R0402]
R166  10K(1%)(NC)  [R0402]
R167  10K(1%)(NC)  [R0402]
R168  5.1K(1%)(NC)  [R0402]
R169  5.1K(1%)  [R0402]
R181  0(1%)  [R0603]
R213  0(1%)  [R0603]
R222  1K(1%)  [R0402]
R223  1K(1%)  [R0402]
R229  10K(1%)  [R0402]
R230  10K(1%)(NC)  [R0402]
TP3  TESTPOINT  [TPC1]
TP4  TESTPOINT  [TPC1]
TP5  TESTPOINT  [TPC1]
TP6  TESTPOINT  [TPC1]
TP7  TESTPOINT  [TPC1]
TP8  TESTPOINT  [TPC1]
TP9  TESTPOINT  [TPC1]
TP10  TESTPOINT  [TPC1]
TP12  TESTPOINT  [TPC1]
TP13  TESTPOINT  [TPC1]
TP14  TESTPOINT  [TPC1]
TP15  TESTPOINT  [TPC1]
TP16  TESTPOINT  [TPC1]
TP17  TESTPOINT  [TPC1]
TP18  TESTPOINT  [TPC1]
TP19  TESTPOINT  [TPC1]
U1  ESP32-C6-MINI-1  [ESP32-C6-MINI-1]
U8  IP101GRI  [qfn32_0p4_4_e2p75]
Y3  25MHz+/-10ppm  [XTAL3225]
sheet 06_SYS_PWR_USB
C65  10uF/10V(20%)  [C0603]
C69  22pF/50V(5%)(NC)  [C0402]
C70  10uF/10V(20%)  [C0603]
C71  10uF/10V(20%)  [C0603]
C72  100uF/10V(20%)  [C1206]
C73  10uF/10V(20%)  [C0603]
C74  0.1uF/50V(10%)  [C0402]
C75  100uF/10V(20%)  [C1206]
C76  1uF/16V(10%)  [C0402]
C79  22uF/10V(20%)  [C0603]
C80  0.1uF/50V(10%)  [C0402]
C110  1uF/16V(10%)  [C0402]
C117  1uF/16V(10%)  [C0402]
D12  RED LED  [LED0603]
D13  LESD5D5.0CT1G  [SOD523]
D14  ESD7951ST5G  [SOD882]
D15  LESD5D5.0CT1G  [SOD523]
D16  ESD7951ST5G  [SOD882]
D17  LESD5D5.0CT1G  [SOD523]
D18  LESD5D5.0CT1G  [SOD523]
D19  LESD5D5.0CT1G  [SOD523]
D20  LESD5D5.0CT1G  [SOD523]
D21  ESD7951ST5G(NC)  [SOD882]
D22  ESD7951ST5G(NC)  [SOD882]
D23  LESD5D5.0CT1G  [SOD523]
D24  LESD5D5.0CT1G  [SOD523]
H1  STD  [HOLE5_3]
H2  STD  [HOLE5_3]
H3  STD  [HOLE5_3]
H4  STD  [HOLE5_3]
J15  USB_TYPEC_16P_F  [USB_TYPEC_16P_F]
J18  USB-02  [292303-6]
J19  USB_TYPEC_16P_F  [USB_TYPEC_16P_F]
J20  USB_TYPEC_16P_F  [USB_TYPEC_16P_F]
L4  2.2uH  [L2520]
Q2  LMBT3906DW1T1G  [SOT-363]
Q3  AO3401A  [SOT23-3]
Q4  AO3401A  [SOT23-3]
Q5  LMBT3906DW1T1G  [SOT-363]
Q6  LMBT3906DW1T1G  [SOT-363]
Q7  AO3401A  [SOT23-3]
R145  10K(1%)  [R0402]
R151  10K(1%)  [R0402]
R152  10K(1%)(NC)  [R0402]
R170  22.1K(1%)  [R0402]
R172  100K(1%)  [R0402]
R173  10K(1%)  [R0402]
R174  0(1%)  [R0603]
R175  5.1K(1%)  [R0402]
R176  10K(1%)  [R0402]
R177  51K(1%)  [R0402]
R178  0(1%)  [R0402]
R179  0(1%)  [R0402]
R180  5.1K(1%)  [R0402]
R182  5.1K(1%)  [R0402]
R183  5.1K(1%)  [R0402]
R184  5.1K(1%)  [R0402]
R185  5.1K(1%)  [R0402]
R186  5.1K(1%)  [R0402]
R187  0(1%)  [R0603]
R216  51K(1%)  [R0402]
R217  10K(1%)  [R0402]
R220  0(1%)  [R0402]
R221  0(1%)  [R0402]
R224  10K(1%)  [R0402]
R225  51K(1%)  [R0402]
SW3  SS-12D10L3  [SS-12D10L3]
TP28  TESTPOINT  [TPC1]
TP30  TESTPOINT  [TPC1]
U9  TPS2051CDBVR  [SOT23-5]
U11  TLV62569  [sot23_0P95_2P6]

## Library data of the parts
C18 C19 C28 C45 C53 C69 = CAPACITOR: Part Number: ES110412265200; Part Type: Capacitor
C20 C54 C61 C70 C71 C82 C87 C91 C93 C95 C98 C100 C102 C104 C107 = CAP
C2 C10 C14 C16 C25 C30 C33 C44 C47 C48 C74 C80 C83-C86 C88-C90 C92 C94 C96 C97 C99 C101 C103 C105 C118 = CAPACITOR: Part Number: ES110451066200; Part Type: Capacitor
C8 C50 C51 C55 C56 = CAPACITOR: Part Number: ES110461046100; Part Type: Capacitor
L1-L4 = INDUCTOR
R8 R9 R22-R33 R35 R37-R50 R53-R56 R59 R61 R69 R71 R72 R74-R82 R85-R94 R97 R100-R108 R110 R112-R118 R122 R127 R128 R131-R136 R138-R144 R149 R150 R153-R161 R163-R170 R172 R178 R179 R190 R194 R196-R199 R202-R207 R212 R220-R223 R227 R228 R231-R234 = RESISTOR
R58 = RESISTOR: Part Number: ES210471000000; Part Type: Resistor
R67 R70 R176 R177 R216 R217 R224-R226 = RESISTOR: Part Number: ES210400000000; Part Type: Resistor
TP1-TP20 TP22-TP27 TP30-TP36 = TESTPOINT: Part Number: ES519900000000
U4 = ESP32-P4_QFN104_ECO5
U7 U11 = TLV62565
Y1 = XTAL_2P
Y2 = XTAL
C7 C15 C46 C63 C65 C72 C73 C75 C76 C110 C117 = CAPACITOR
J1 = CON20X2
J5 = DSI_1-1734248-5
J9 = CSI_1-1734248-5
R1 R3-R6 R10-R12 R18 R111 R123 R145 R151 R152 R200 R208 R209 = RESISTOR: Part Number: ES210441000000; Part Type: Resistor
R98 R109 = RESISTOR: Part Number: ES210432200000; Part Type: Resistor
SW1 SW2 = SW_SP_4P
U2 = FLASH_4
C21-C24 C26 C27 C29 C32 C34-C43 C57-C60 C62 C64 C66-C68 C77 C78 C81 C108 C109 C111-C116 = CAP_NP
C1 C31 C49 C79 = CAPACITOR: Part Number: ES110671057000; Part Type: Capacitor
J7 = MIC_ELECT
J16 = SPEAKER_0
R51 R52 R57 R60 R62-R66 R68 R73 R83 R84 R146-R148 R171 = RESISTOR_0
R99 R174 R181 R187 R213 R229 R230 = RESISTOR: Part Number: ES210600000000; Part Type: Resistor
U3 = ES8311
U5 = LDO_SOT23-5_3: CODE12: ES41.14.02.07.00.00; Part Number: ES41140207000000; Part Type: Power ICs
U10 = LM25085MY_2
D3-D8 D10 D11 = DIODE_BI_DIR: Part Number: ES313200100000; Part Type: Diode
J2 = CON3X2
J17 = RJ45_trans_100_2LED
J21 = TF_SD_SOCKET
Q3 Q4 Q7 Q8 = PMOS
R16 R17 R19 R21 R34 R36 = RESISTOR: Part Number: ES210445100000; Part Type: Resistor
U1 = ESP32-C6-MINI-1
U8 = ESP8080_6
Y3 = X1_0
D12 = DIODE_LIGHT: Part Number: ES313400100000; Part Type: Diode
D13 D16-D20 D22 D23 = DIODE_BI_DIR: CODE12: ES31.32.0020.00.0.0; Part Number: ES31320020000000; Part Type: Diode
D14 D21 D24 = DIODE_BI_DIR: CODE12: ES31.32.0020.00.0.0; Part Type: Diode
D15 = DIODE_BI_DIR: Part Number: ES313200200000; Part Type: Diode
H1-H4 = STD
J15 J19 J20 = USB_TYPEC_16P_F: CODE12: ES52.22.0020.00.00; Part Number: ES52220020000000; Part Type: Connector
J18 = USB_0
Q2 Q5 Q6 = DUAL_PNP
R173 = RESISTOR: Part Number: ES210451000000; Part Type: Resistor
R175 R180 R182-R186 = RESISTOR: Part Number: ES210435100000; Part Type: Resistor
SW3 = SS-12D10L3
TP28 = TESTPOINT_3: CODE12: ES51.99.0010.00.00; Part Number: ES51990010000000
U9 = AP22802_2

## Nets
A3V3: C31.1 C33.1 R68.2 U5.5(OUT)
AGND: C21.2 C22.2 C23.2 C24.2 C26.2 C27.2 C29.2 C35.1 C36.1 C37.1 C38.2 C41.2 C42.1 C43.2 C57.2 C60.2 C62.2 C63.2 C66.2 C67.1 C77.1 C81.2 J16.3 J16.4 R57.1 R66.2 R99.1 R148.2 U3.5(DGND) U3.10(AGND) U3.21(PAD) U10.7(GND)
AVDD: C35.2 R68.1 U3.11(AVDD)
DVDD: C21.1 C22.1 R51.2 U3.3(PVDD) U3.4(DVDD)
GND: C1.2 C2.2 C7.2 C8.2 C10.2 C14.2 C15.2 C16.2 C18.2 C19.2 C20.2 C25.2 C28.2 C30.2 C31.2 C33.2 C44.2 C45.2 C46.2 C47.2 C48.2 C49.2 C50.2 C51.2 C54.2 C55.2 C56.2 C61.2 C64.2 C65.2 C68.2 C70.2 C71.2 C72.2 C73.2 C74.2 C75.2 C76.2 C79.2 C80.2 C82.2 C83.2 C84.2 C85.2 C86.2 C87.2 C88.2 C89.2 C90.2 C91.2 C92.2 C93.2 C94.2 C95.2 C96.2 C97.2 C98.2 C99.2 C100.2 C101.2 C102.2 C103.2 C104.2 C105.2 C107.2 C108.2 C109.2 C110.2 C111.2 C112.2 C113.2 C114.2 C115.2 C116.2 C117.2 C118.2 D3.1 D4.1 D5.1 D6.1 D7.1 D8.1 D10.1 D11.1 D12.2(CATHODE) D13.1 D14.1 D15.1 D16.1 D17.1 D18.1 D19.1 D20.1 D21.1 D22.1 D23.1 D24.1 H1.1 H2.1 H3.1 H4.1 J1.6 J1.9 J1.14 J1.20 J1.25 J1.30 J1.34 J1.39 J2.4 J5.1(GND) J5.4(GND) J5.7(GND) J5.10(GND) J5.13(GND) J9.1(GND) J9.4(GND) J9.7(GND) J9.10(GND) J15.1(A1_G) J15.2(B12_G) J15.15(B1_G) J15.16(A12_G) J17.8(GND) J18.4(GND) J19.1(A1_G) J19.2(B12_G) J19.15(B1_G) J19.16(A12_G) J20.1(A1_G) J20.2(B12_G) J20.15(B1_G) J20.16(A12_G) J21.6(VSS) J21.10(G1) J21.11(G2) J21.12(G3) J21.13(G4) R99.2 R138.2 R140.1 R152.1 R153.2 R154.2 R156.2 R165.2 R166.2 R169.2 R170.2 R176.1 R177.1 R180.1 R181.2 R182.1 R183.1 R184.1 R185.1 R186.1 R187.2 R202.2 R203.2 R216.1 R217.1 R223.2 R224.1 R225.1 R229.1 R234.2 SW1.1 SW2.1 TP1.1 TP3.1 TP12.1 U1.1(GND) U1.2(GND) U1.11(GND) U1.14(GND) U1.36(GND) U1.37(GND) U1.38(GND) U1.39(GND) U1.40(GND) U1.41(GND) U1.42(GND) U1.43(GND) U1.44(GND) U1.45(GND) U1.46(GND) U1.47(GND) U1.48(GND) U1.49(EPAD) U1.50(GND) U1.51(GND) U1.52(GND) U1.53(GND) U2.4(GND) U2.9(EPAD) U4.105(GND) U5.2(GND) U7.2(GND) U8.33(E-PAD) U9.2(GND) U11.2(GND) Y2.2(GND) Y2.4(GND) Y3.2(GND) Y3.4(GND)
GND_EARTH: J15.17(E_G1) J15.18(E_G2) J15.19(E_G3) J15.20(E_G4) J18.5(GND) J18.6(GND) J19.17(E_G1) J19.18(E_G2) J19.19(E_G3) J19.20(E_G4) J20.17(E_G1) J20.18(E_G2) J20.19(E_G3) J20.20(E_G4) R187.1
GND_RJ45_EARTH: J17.SHD1 J17.SHD2 R181.1
VBUS_EN: R145.2 R152.2 U9.4(EN)
VBUS_OUT: C72.1 C73.1 C74.1 C75.1 D15.2 J18.1(VBUS) U9.1(OUT)
VCC_5V: C48.1 C49.1 C65.1 C71.1 J1.2 J1.4 R145.1 R151.1 R171.2 R173.1 R175.2 R226.2 SW3.1 U5.1(VIN) U9.5(IN) U11.4(VIN)
VDD_FLASH: C16.1 C20.1 C25.1 R18.2 R35.2 R37.2 U2.8(VCC) U4.30(VDD_FLASHIO)
25M_XI: R161.1 U8.2(X1)
25M_XO: R158.1 U8.3(X2)
ADCVREF: C43.1 R73.2 U3.15(ADCVREF)
BAT: R196.1 TP2.1
C6_EN: C8.1 J2.1 R4.1 R76.2 U1.8(EN)
C6_IO8: R10.1 U1.22(IO8)
C6_IO9: J2.6 U1.23(IO9)
C6_U0RXD: J2.5 U1.30(RXD0)
C6_U0TXD: J2.3 U1.31(TXD0)
C6_WAKEUP: R30.2 U1.5(IO2)
CNN_GPIO0: J1.23 R199.1
CNN_GPIO1: J1.22 R197.1
CNN_GPIO2: J1.21 R22.1
CNN_GPIO3: J1.19 R48.1
CNN_GPIO4: J1.18 R31.1
CNN_GPIO5: J1.16 R47.1
CNN_GPIO6: J1.15 R29.1
CNN_GPIO7: J1.3 R46.1
CNN_GPIO8: J1.5 R28.1
CNN_GPIO20: J1.13 R33.1
CNN_GPIO21: J1.11 R39.1
CNN_GPIO22: J1.12 R32.1
CNN_GPIO23: J1.7 R38.1
CNN_GPIO26: J1.31 R228.2
CNN_GPIO27: J1.38 R227.2
CNN_GPIO32: J1.26 R116.2
CNN_GPIO33: J1.29 R134.2
CNN_GPIO36: J1.24 R112.2
CNN_GPIO37: J1.8 R136.2
CNN_GPIO38: J1.10 R118.2
CNN_GPIO45: J1.40 R100.2
CNN_GPIO46: J1.36 R97.2
CNN_GPIO47: J1.37 R94.2
CNN_GPIO48: J1.33 R93.2
CNN_GPIO53: J1.35 R85.1
CNN_GPIO54: J1.32 R80.1
Codec_CE: R57.2 R60.1 U3.20(CE)
COL: R149.2 R153.1 U8.4(COL/RMII)
CRS: R154.1 R155.2 U8.20(CRS/LEDMOD)
CSI_A_CLKN: J9.8(CLK_CN) R86.2
CSI_A_CLKP: J9.9(CLK_CP) R82.2
CSI_A_DATA0N: J9.2(DN0) R78.2
CSI_A_DATA0P: J9.3(DP0) R81.2
CSI_A_DATA1N: J9.5(DN1) R88.2
CSI_A_DATA1P: J9.6(DP1) R90.2
CSI_CLKN: R86.1 U4.45(CSI_CLKN)
CSI_CLKP: R82.1 U4.44(CSI_CLKP)
CSI_DATA0N: R78.1 U4.42(CSI_DATAN0)
CSI_DATA0P: R81.1 U4.43(CSI_DATAP0)
CSI_DATA1N: R88.1 U4.46(CSI_DATAN1)
CSI_DATA1P: R90.1 U4.47(CSI_DATAP1)
CSI_IO0: J9.11(CAM_IO0) R123.2
CSI_IO1: J9.12(CAM_IO1) R111.2
CSI_REXT: R203.1 U4.48(CSI_REXT)
DACVREF: C42.2 U3.14(DACVREF)
DSI_A_CLKN: J5.5(CLK_CN) R72.1
DSI_A_CLKP: J5.6(CLK_CP) R74.1
DSI_A_DATA0N: J5.8(DN0) R77.1
DSI_A_DATA0P: J5.9(DP0) R75.1
DSI_A_DATA1N: J5.2(DN1) R71.1
DSI_A_DATA1P: J5.3(DP1) R69.1
DSI_CLKN: R72.2 U4.37(DSI_CLKN)
DSI_CLKP: R74.2 U4.38(DSI_CLKP)
DSI_DATA0N: R77.2 U4.40(DSI_DATAN0)
DSI_DATA0P: R75.2 U4.39(DSI_DATAP0)
DSI_DATA1N: R71.2 U4.36(DSI_DATAN1)
DSI_DATA1P: R69.2 U4.35(DSI_DATAP1)
DSI_REXT: R202.1 U4.34(DSI_REXT)
EN_DCDC: U4.79(EN_DCDC) U7.1(EN/PG)
ESP_3V3: C1.1 C2.1 C7.1 C10.1 C46.1 C47.1 C83.1 C85.1 C87.1 C88.1 C90.1 C95.1 C96.1 C97.1 C103.1 J1.1 J1.17 J5.14(3V3) J5.15(3V3) J9.15(3V3) Q8.2(S) R1.1 R3.1 R4.2 R5.1 R6.1 R10.2 R11.1 R12.1 R35.1 R51.1 R60.2 R98.1 R109.1 R111.1 R123.1 R127.1 R174.2 R198.1 R208.2 R209.2 R213.1 R230.2 R233.2 U1.3(3V3) U4.9(VDD_LP) U4.21(VDD_IO_0) U4.62(VDD_IO_4) U4.75(VDD_LDO) U4.77(VDD_DCDCC) U4.96(VDD_IO_6) U4.101(VDD_ANA)
ESP_EN: C30.1 R200.2 SW1.3 TP23.1 U4.103(CHIP_PU)
ESP_I2C_SCL: R9.1 R52.1 R106.1 R109.2 R190.1
ESP_I2C_SDA: R8.1 R62.1 R98.2 R101.1 R194.1
ESP_LDO_VO1: C56.1 R37.1 TP26.1 U4.71(VDDO_FLASH)
ESP_LDO_VO2: C50.1 C104.1 C105.1 TP24.1 U4.59(VDD_PSRAM_0) U4.67(VDD_PSRAM_1) U4.72(VDDO_PSRAM)
ESP_LDO_VO3: C55.1 C91.1 C92.1 C93.1 TP27.1 U4.41(VDD_MIPI_DPHY) U4.73(VDDO_3)
ESP_LDO_VO4: C51.1 C101.1 C102.1 R17.1 R19.1 R21.1 R34.1 R36.1 TP25.1 U4.74(VDDO_4) U4.85(VDD_IO_5)
ESP_VBAT: C82.1 C84.1 R196.2 R198.2 R200.1 U4.102(VDD_BAT)
ESP_VDD_HP: C53.1 C61.1 C86.1 C89.1 C94.1 C107.1 L1.2 R128.1 R232.2 U4.26(VDD_HP_0) U4.76(VDD_HP_2) U4.91(VDD_HP_3)
FB_DCDC: C53.2 R128.2 R138.1 U4.78(FB_DCDC) U7.5(FB)
FLASH_CK: R49.2 U4.32(FLASH_CK)
FLASH_CK_A: R49.1 U2.6(CLK)
FLASH_CS: R56.2 U4.27(FLASH_CS)
FLASH_CS_A: R18.1 R56.1 U2.1(/CS)
FLASH_D: R53.2 U4.33(FLASH_D)
FLASH_D_A: R53.1 U2.5(DI)
FLASH_HD: R54.2 U4.31(FLASH_HOLD)
FLASH_HD_A: R54.1 U2.7(/HOLD)
FLASH_Q: R50.2 U4.28(FLASH_Q)
FLASH_Q_A: R50.1 U2.2(DO)
FLASH_WP: R55.2 U4.29(FLASH_WP)
FLASH_WP_A: R55.1 U2.3(/WP)
GPIO0: R61.1 R199.2 U4.104(GPIO0)
GPIO1: R59.1 R197.2 U4.1(GPIO1)
GPIO2: R22.2 U4.2(GPIO2)
GPIO3: R48.2 U4.3(GPIO3)
GPIO4: R31.2 U4.4(GPIO4)
GPIO5: R47.2 U4.5(GPIO5)
GPIO6: R29.2 R30.1 U4.6(GPIO6)
GPIO7: R46.2 R194.2 U4.7(GPIO7)
GPIO8: R28.2 R190.2 U4.8(GPIO8)
GPIO9: R45.2 U4.10(GPIO9)
GPIO10: R27.2 U4.11(GPIO10)
GPIO11: R44.2 U4.12(GPIO11)
GPIO12: R26.2 U4.13(GPIO12)
GPIO13: R43.2 U4.14(GPIO13)
GPIO14: R25.2 U4.15(GPIO14)
GPIO15: R42.2 U4.16(GPIO15)
GPIO16: R24.2 U4.17(GPIO16)
GPIO17: R41.2 U4.18(GPIO17)
GPIO18: R23.2 U4.19(GPIO18)
GPIO19: R40.2 U4.20(GPIO19)
GPIO20: R33.2 U4.22(GPIO20)
GPIO21: R39.2 U4.23(GPIO21)
GPIO22: R32.2 U4.24(GPIO22)
GPIO23: R38.2 U4.25(GPIO23)
GPIO24: R104.1 U4.52(GPIO24)
GPIO25: R105.1 U4.53(GPIO25)
GPIO26: R113.1 R228.1 U4.55(GPIO26)
GPIO27: R131.1 R227.1 U4.56(GPIO27)
GPIO28: R114.1 U4.57(GPIO28)
GPIO29: R132.1 U4.58(GPIO29)
GPIO30: R115.1 U4.60(GPIO30)
GPIO31: R133.1 U4.61(GPIO31)
GPIO32: R116.1 U4.63(GPIO32)
GPIO33: R134.1 U4.64(GPIO33)
GPIO34: R117.1 R205.2 U4.65(GPIO34)
GPIO34_BOOTMODE: R205.1 TP34.1
GPIO35: R135.1 R207.1 U4.66(GPIO35)
GPIO35_BOOTMODE: C44.1 R207.2 R208.1 SW2.3 TP22.1
GPIO36: R112.1 R204.1 U4.68(GPIO36)
GPIO36_BOOTMODE: R204.2 R209.1 TP33.1
GPIO37: R136.1 R212.1 U4.69(GPIO37)
GPIO37_BOOTMODE: R212.2 TP36.1
GPIO38: R118.1 R206.1 U4.70(GPIO38)
GPIO38_BOOTMODE: R206.2 TP35.1
GPIO39: R122.1 U4.80(GPIO39)
GPIO40: R110.1 U4.81(GPIO40)
GPIO41: R108.1 U4.82(GPIO41)
GPIO42: R107.1 U4.83(GPIO42)
GPIO43: R103.1 U4.84(GPIO43)
GPIO44: R102.1 U4.86(GPIO44)
GPIO45: R100.1 R231.1 U4.87(GPIO45)
GPIO46: R97.1 U4.88(GPIO46)
GPIO47: R94.1 U4.89(GPIO47)
GPIO48: R93.1 U4.90(GPIO48)
GPIO49: R92.1 U4.92(GPIO49)
GPIO50: R91.1 U4.93(GPIO50)
GPIO51: R89.1 U4.94(GPIO51)
GPIO52: R87.1 U4.95(GPIO52)
GPIO53: R79.1 R85.2 U4.97(GPIO53)
GPIO54: R76.1 R80.2 U4.98(GPIO54)
I2S_ASDOUT: R44.1 U3.7(ASDOUT)
I2S_DSDIN: R45.1 U3.9(DSDIN)
I2S_LRCK: C29.1 R27.1 U3.8(LRCK)
I2S_MCLK: C23.1 R43.1 U3.2(MCLK)
I2S_SCLK: C26.1 R26.1 U3.6(SCLK/DMIC_SCL)
MDC: R133.2 R160.2 U8.22(MDC)
MDIO: R87.2 R163.2 U8.23(MDIO)
MICN: C34.1 R64.2 R65.1
MICP: C32.1 J7.1(+) R63.1 TP11.1
OUTN: C57.1 C58.1 R84.2
OUTP: C59.1 C60.1 R83.2
PA_CTRL: R79.2 R148.1 U10.1(CTRL)
PA_INL+: R147.2 U10.3(IN+)
PA_INL-: R146.2 U10.4(IN-)
PA_OUTL+: L3.2 U10.8(OUT+)
PA_OUTL-: L2.2 U10.5(OUT-)
PA_PVDD1: C63.1 C66.1 C67.2 R171.1 U10.6(VCC)
PHY_3V3: C108.1 C109.1 C112.1 C114.1 J17.12(YLED+) R141.1 R149.1 R155.1 R157.1 R160.1 R163.1 R164.1 R167.1 R168.1 R213.2 U8.13(VDD_IO) U8.31(AVDD33)
PHY_AD0: R141.2 R222.2 U8.11(LED0/PHY_AD0)
PHY_AD3: J17.9(GLED+) R140.2 U8.12(LED3/PHY_AD3)
PHY_ISET: R165.1 U8.25(ISET)
PHY_RSTN: R89.2 R166.1 R167.2 U8.32(RESET_N)
PHY_TESTON: R164.2 U8.24(TEST_ON)
RD+: J17.3(RXD+) U8.27(MDI_RP)
RD-: J17.6(RXD-) U8.26(MDI_RN)
RMII_CLK: R91.2 R139.1 R142.1
RMII_CRSDV: R114.2 R150.1
RMII_RXD0: R132.2 R144.1
RMII_RXD1: R115.2 R143.1
RMII_TXD0: R117.2 U8.9(TXD0)
RMII_TXD1: R135.2 U8.8(TXD1)
RMII_TXEN: R92.2 U8.5(TXEN)
RXER: R156.1 R157.2 U8.21(RXER/INTR_32)
SD1_CLK: D6.2 J21.5(CLK) R103.2 TP15.1
SD1_CMD: D4.2 J21.3(CMD) R17.2 R102.2 TP14.1
SD1_D0: D11.2 J21.7(DATA0) R36.2 R122.2 TP19.1
SD1_D1: D10.2 J21.8(DATA1) R34.2 R110.2 TP18.1
SD1_D2: D8.2 J21.1(DATA2) R21.2 R108.2 TP17.1
SD1_D3: D7.2 J21.2(CD/DATA3) R19.2 R107.2 TP16.1
SD1_VDD: C14.1 C15.1 D3.2 J21.4(VDD) Q8.3(D) R16.1 TP13.1
SD2_CLK: R12.2 R23.1 TP5.1 U1.25(IO19)
SD2_CMD: R11.2 R40.1 TP4.1 U1.24(IO18)
SD2_D0: R6.2 R25.1 TP9.1 U1.26(IO20)
SD2_D1: R5.2 R42.1 TP8.1 U1.27(IO21)
SD2_D2: R3.2 R24.1 TP7.1 U1.28(IO22)
SD2_D3: R1.2 R41.1 TP6.1 U1.29(IO23)
SD_DET: D5.2 J21.9(CD) R16.2 TP10.1
SD_PWRn: Q8.1(G) R229.2 R230.1 R231.2
TD+: J17.1(TXD+) U8.30(MDI_TP)
TD-: J17.2(TXD-) U8.29(MDI_TN)
TXER: R168.2 R169.1 U8.1(TXER/FXSD)
USB0_5V: C76.1 D20.2 J20.3(A4_VBUS) J20.4(B9_VBUS) J20.13(B4_VBUS) J20.14(A9_VBUS) Q2.1(1E) Q3.3(D)
USB1_5V: C117.1 D19.2 J19.3(A4_VBUS) J19.4(B9_VBUS) J19.13(B4_VBUS) J19.14(A9_VBUS) Q6.1(1E) Q7.3(D)
USB1P1_N: D17.2 J19.7(B7_DN2) J19.9(A7_DN1) R104.2
USB1P1_N_2: D24.2 J20.7(B7_DN2) J20.9(A7_DN1) R113.2
USB1P1_P: D18.2 J19.8(A6_DP1) J19.10(B6_DP2) R105.2
USB1P1_P_2: D23.2 J20.8(A6_DP1) J20.10(B6_DP2) R131.2
USB2_5V: C110.1 D13.2 J15.3(A4_VBUS) J15.4(B9_VBUS) J15.13(B4_VBUS) J15.14(A9_VBUS) Q4.3(D) Q5.1(1E)
USB_5V: C79.1 C80.1 Q2.4 Q3.2(S) Q4.2(S) Q5.4 Q6.4 Q7.2(S) SW3.2
USB_DM: R221.2 U4.49(DM)
USB_DM_A: D22.2 J18.2(D-) R178.2 R221.1
USB_DM_C: D14.2 J15.7(B7_DN2) J15.9(A7_DN1) R178.1
USB_DP: R220.2 R234.1 U4.50(DP)
USB_DP_A: D21.2 J18.3(D+) R179.2 R220.1
USB_DP_C: D16.2 J15.8(A6_DP1) J15.10(B6_DP2) R179.1
VMID: C37.2 U3.16(VMID)
XTAL_N: R70.1 U4.99(XTAL_N)
XTAL_P: R67.1 U4.100(XTAL_P)
N16934509: C28.1 R67.2 Y2.1(XIN)
N16934523: C45.1 R70.2 Y2.3(XOUT)
N17578381: D12.1(ANODE) R175.1
N18064827: C98.1 C99.1 C100.1 R233.1 U4.51(VDD_USBPHY)
N18110516: C19.1 R58.1 R61.2 Y1.2
N18110531: C18.1 R58.2 R59.2 Y1.1
N18193754: C54.1 R127.2 U7.4(VIN)
N18193822: L1.1 U7.3(SW)
N18248775: R151.2 TP28.1 U9.3(FLG)
N18251395: Q6.2 Q6.5 Q6.6 R224.2
N18251818: Q6.3 Q7.1(G) R225.2
N18253640: Q5.2 Q5.5 Q5.6 R217.2
N18253683: Q4.1(G) Q5.3 R216.2
N18255493: J15.6(A5_CC1) R180.2
N18255499: J15.12(B5_CC2) R182.2
N18256275: J19.6(A5_CC1) R184.2
N18256281: J19.12(B5_CC2) R183.2
N18262730: C69.2 R170.1 R172.2 U11.5(FB)
N18262736: C69.1 C70.1 L4.2 R172.1 R174.1 TP30.1
N18262777: R173.2 U11.1(EN/PG)
N18262785: L4.1 U11.3(SW)
N18266990: C115.1 J17.4(TXCT)
N18266994: C116.1 J17.5(RXCT)
N18267072: J17.10(GLED-) R223.1
N18267076: J17.11(YLED-) R222.1
N18267340: R143.2 U8.17(RXD1)
N18267342: R144.2 U8.18(RXD0)
N18267344: R150.2 U8.19(RXDV/CRS_DV/FX_HEN)
N18267350: R139.2 U8.14(RXCLK/50M_CLKO)
N18267444: C111.1 C113.1 U8.28(REGOUT)
N18267472: R142.2 U8.10(TXCLK/50M_CLKI)
N18299901: C32.2 U3.18(MIC1P/DMIC_SDA)
N18299903: C34.2 U3.17(MIC1N)
N18300035: C24.1 R52.2 U3.1(CCLK)
N18300076: C27.1 R62.2 U3.19(CDATA)
N18300564: J7.2(-) R64.1 R66.1 TP20.1
N18300580: C36.2 R63.2 R65.2 R73.1
N18302373: C40.2 C41.1 U3.13(OUTN)
N18302385: C38.1 C39.2 U3.12(OUTP)
N18302434: C40.1 R84.1
N18302436: C39.1 R83.1
N18379689: C64.1 R158.2 R159.1 Y3.1(XIN)
N18379734: C68.1 R159.2 R161.2 Y3.3(XOUT)
N18399134: Q2.2 Q2.5 Q2.6 R176.2
N18399180: Q2.3 Q3.1(G) R177.2
N18405255: J20.6(A5_CC1) R185.2
N18405261: J20.12(B5_CC2) R186.2
N18412230: J5.11(SCL0) R9.2
N18412242: J5.12(SDA0) R8.2
N18422156: C62.1 U10.2(Bypass)
N18423897: C77.2 C78.2 J16.1 L3.1 TP32.1
N18423915: C78.1 C81.1 J16.2 L2.1 TP31.1
N18424033: C59.2 R147.1
N18424043: C58.2 R146.1
N18497724: J9.13(SCL0) R106.2
N18497727: J9.14(SDA0) R101.2
N18604768: R226.1 U5.3(EN)
N18792940: C118.1 R232.1 U4.54(VDD_HP_1)

Not connected (* = marked no-connect by the designer): J1 27* 28*; J2 2*; J5 16* 17* 18* 19* 20* 21* 22* 23* 24* 25* 26* 27* 28* 29* 30*; J9 16* 17* 18* 19* 20* 21* 22* 23* 24* 25* 26* 27* 28* 29* 30*; J15 5(B8_SBU2)* 11(A8_SBU1)*; J17 7(NC)*; J19 5(B8_SBU2)* 11(A8_SBU1)*; J20 5(B8_SBU2)* 11(A8_SBU1)*; SW1 2* 4*; SW2 2* 4*; SW3 3*; U1 4(NC1)* 6(IO3)* 7(NC2)* 9(IO4)* 10(IO5)* 12(IO0)* 13(IO1)* 15(IO6)* 16(IO7)* 17(IO12)* 18(IO13)* 19(IO14)* 20(IO15)* 21(NC3)* 32(NC4)* 33(NC5)* 34(NC6)* 35(NC7)*; U5 4(NR/FB)*; U8 6(TXD3)* 7(TXD2)* 15(RXD3)* 16(RXD2)*

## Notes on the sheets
sheet 1
- Design Block:
sheet 2
- MDH:2.3.3.400001552EL
- 1V8/3V3
- 3V3(Analog)
- 1V1~1V3(Core)
- 3V3(BAT)
- 1V8/3V3(SDIO)
- 3V3(DCDC)
- 1V1~1V3(Core)
- 3V3(LDO)
- 3V3(RTC)
- 1V8/3V3
- 1V8/3V3
- 1V8(PSRAM)
- 1V1~1V3(Core)
- 3V3(USB2)
- 1V8/3V3(Flash)
- 2V5(MIPI)
sheet 3
- Codec:
- MIC:
- RC circuit to avoid errors
  during I2C read and write
- PA&SPEAKER:
- 3.3V LDO For AVDD:
sheet 4
- RJ45 with Trans
- WiFi & BT Module:
- ETHERNET PHY IC
- Built-in 49R9
  on MDI_xx
- ESP-Prog Connector
- PHY_RSTN is active low.
  Set low to PHY_RSTN pin for
  at least 10ms will reset all
  functions available in
  IP101GRI.
- MicroSD Card：
- PHY MODE CONFIG
- VDDIO(1.8V/3.3V)
- COL/RMII
  0: MII Mode
  1: RMII Mode (default)
  TEST_ON
  1: Enable Test mode.
  NC: Normal operation (default)
  RXER/INTR32
  1: INTR funtion (default)
  0: RXER funtion
  CRS/LEDMOD
  1: LED mode 2 (default)
  0: LED mode 1
  TXER/FXSD
  1: FXSD
  0: TXER (default)
  Default: TXER
  PHY Address
  0b(0xx1)
- MicroSD Card SPI mode:
  1. DAT3 works as CS(chip select);
  2. CMD works as DI(Data In);
  3. CLK works as Clock;
  4. DAT0 works as DO(Data out).
sheet 5
- FLASH:
- Boot Strapping Pins:
- Reset Button:
- 3V3(Flash)
- Boot Button:
- SOP-8 / WSON 6X8
- Pin Header For GPIOs:
- CSI Connector:
- DSI Connector:
- IO0, Reset, 3.3V
- IO1, Strobe, 3.3V
sheet 6
- USB High Speed & Power in:
- USB Serial/JTAG & Power in:
- USB Full Speed Slave & Power in:
- Ideal Diodes：
- 3V3 DC-DC：
- 2A Max
- USB High Speed Host:
- Jumper@J10
- Limit current 500mA
